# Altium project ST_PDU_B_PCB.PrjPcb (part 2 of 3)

## Sheet GroupB.SchDoc: ST PDU - Group B
size A3; Author: EMEA - ADG - M&A; Organization: STMicroelectronics; Address1: Pobrezni 3; Address2: 186 00  Prague 8; Address3: Czech Republic; Revision: 2.3; SheetNumber: 8; SheetTotal: 14
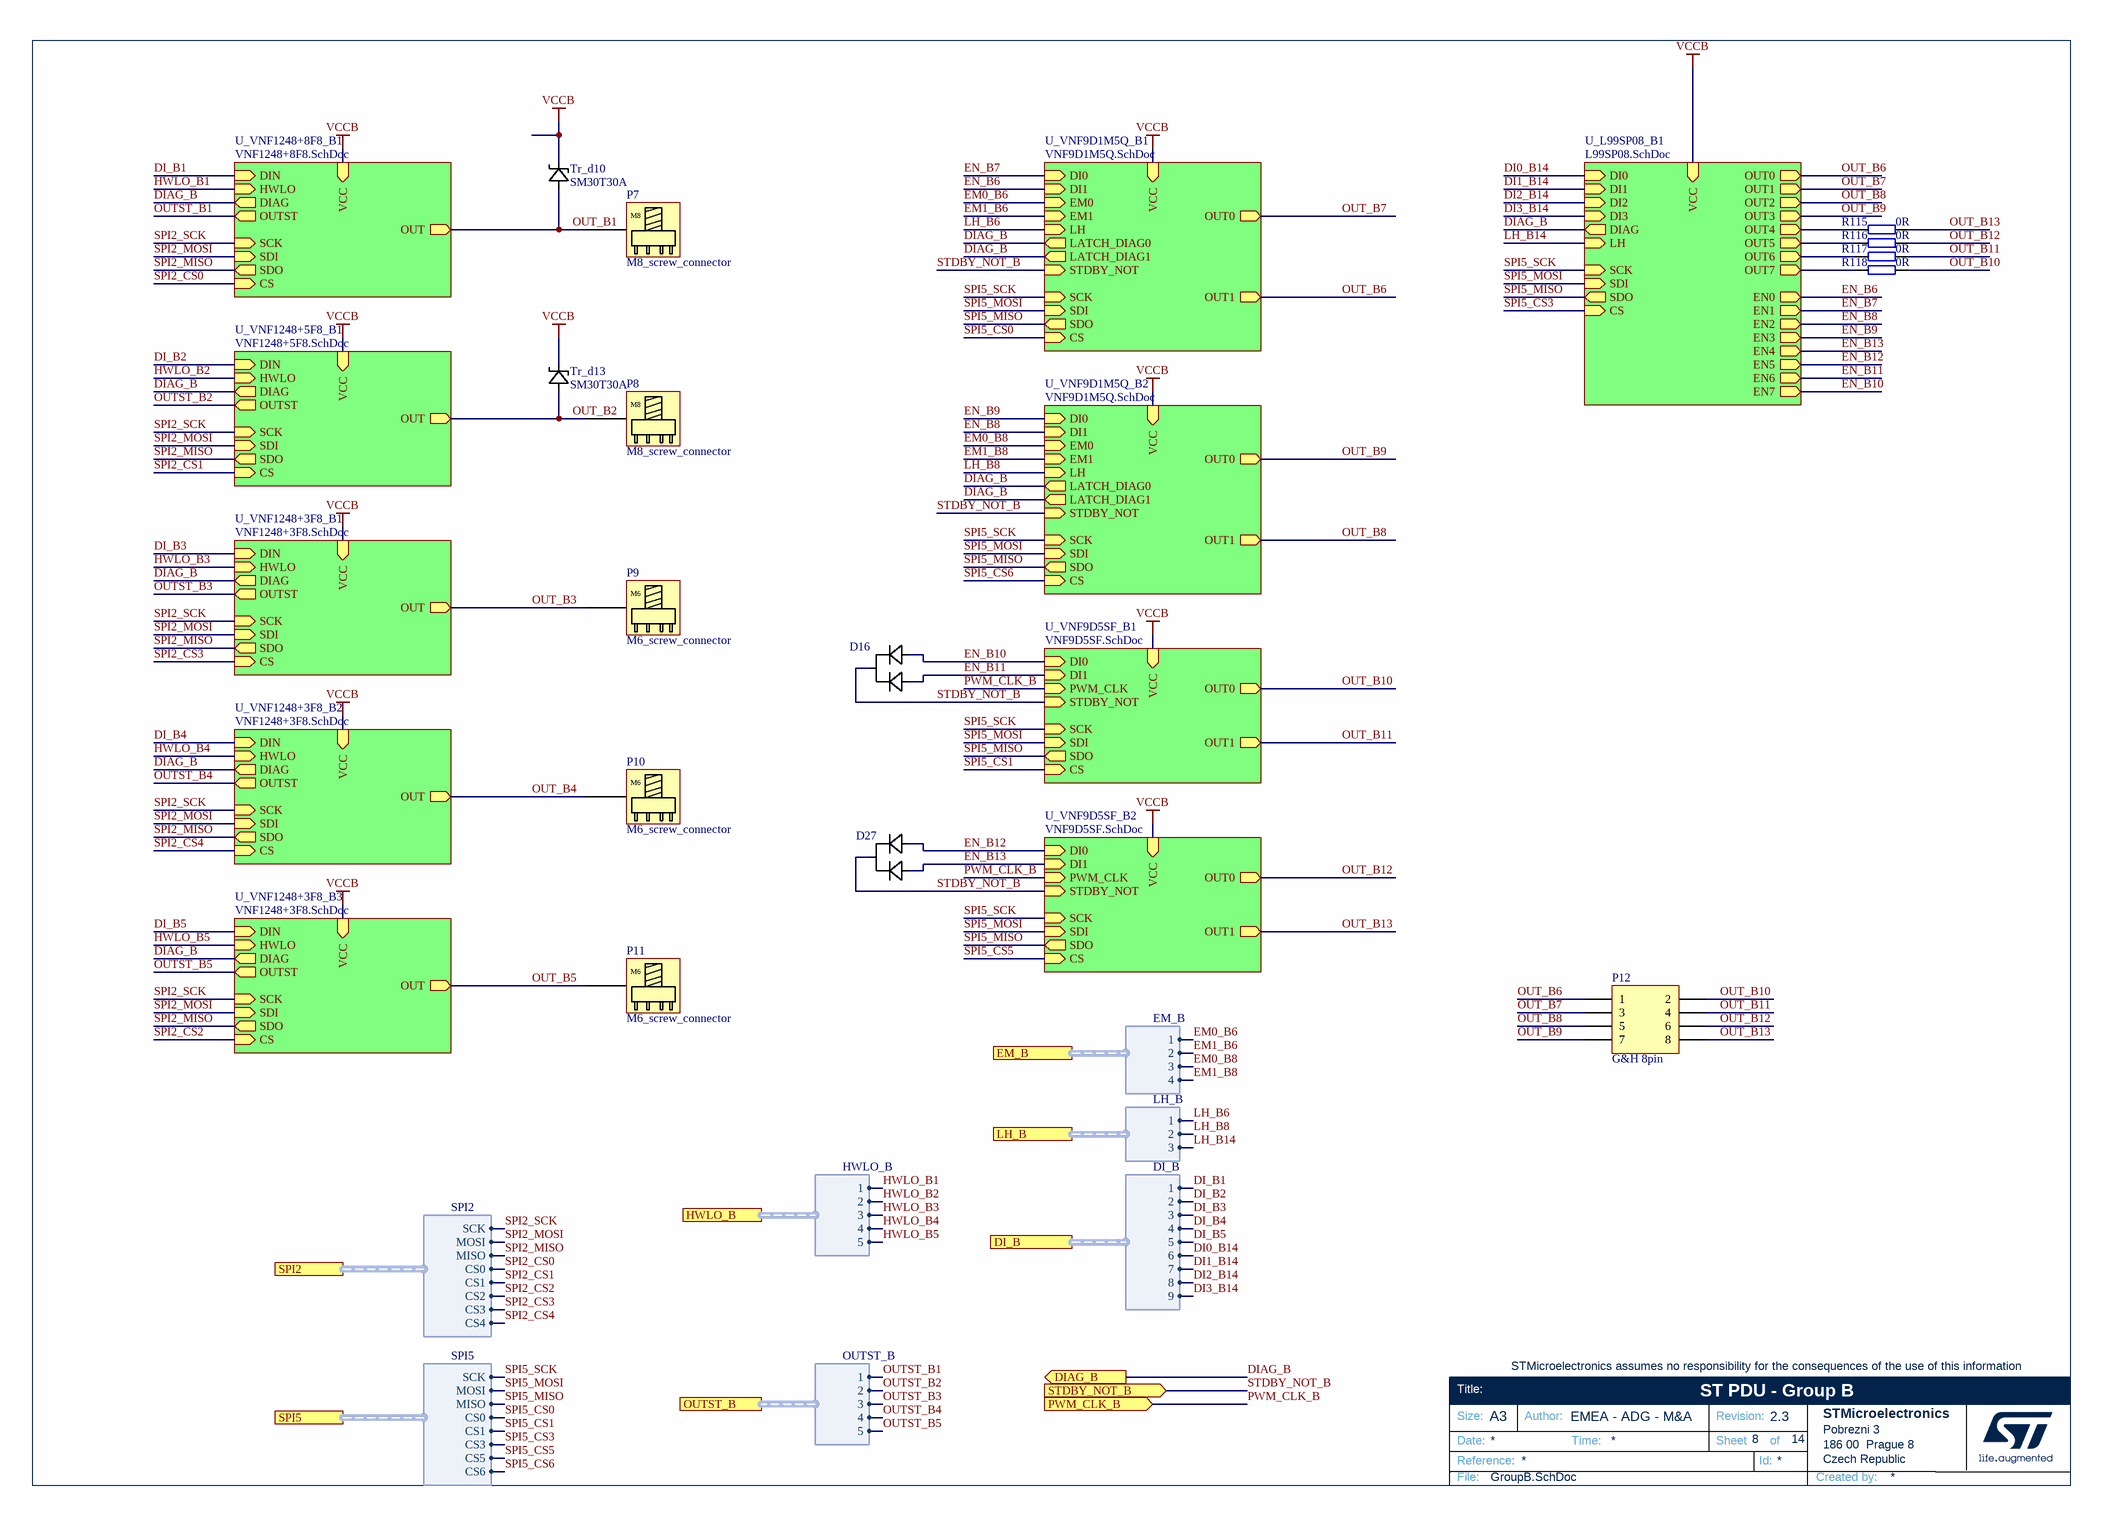
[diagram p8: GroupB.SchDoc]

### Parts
D16  BAT54-Y  [SOT323-3L_STM]  (value not drawn)
D27  BAT54-Y  [SOT323-3L_STM]  (value not drawn)
P7  M8_screw_connector  [MTConn Power Tower M8]
P8  M8_screw_connector  [MTConn Power Tower M8]
P9  M6_screw_connector  [MTConn Power Tower M6]
P10  M6_screw_connector  [MTConn Power Tower M6]
P11  M6_screw_connector  [MTConn Power Tower M6]
P12  value G&H 8pin  [MTConn GH 8pin]  (hidden comment: GH 8pin)
R115  0R  [R0603_round]
R116  0R  [R0603_round]
R117  0R  [R0603_round]
R118  0R  [R0603_round]
Tr_d10  SM30T30A  [SMC]
Tr_d13  SM30T30A  [SMC]

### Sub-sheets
U_L99SP08_B1 = L99SP08.SchDoc: CS (in), SCK (in), SDI (in), SDO (out), OUT1 (out), OUT2 (out), OUT3 (out), OUT0 (out), DI0 (in), DI1 (in), DI2 (in), DI3 (in), LH (in), DIAG (out), VCC (in), EN1 (out), EN2 (out), EN3 (out), EN0 (out), EN5 (out), EN6 (out), EN7 (out), EN4 (out), OUT5 (out), OUT6 (out), OUT7 (out), OUT4 (out)
U_VNF9D1M5Q_B1 = VNF9D1M5Q.SchDoc: CS (in), OUT0 (out), OUT1 (out), SCK (in), SDI (in), SDO (out), EM0 (in), EM1 (in), DI0 (in), DI1 (in), LATCH_DIAG0 (out), LATCH_DIAG1 (out), LH (in), VCC (in), STDBY_NOT (in)
U_VNF9D1M5Q_B2 = VNF9D1M5Q.SchDoc: CS (in), OUT0 (out), OUT1 (out), SCK (in), SDI (in), SDO (out), EM0 (in), EM1 (in), DI0 (in), DI1 (in), LATCH_DIAG0 (out), LATCH_DIAG1 (out), LH (in), VCC (in), STDBY_NOT (in)
U_VNF9D5SF_B1 = VNF9D5SF.SchDoc: OUT0 (out), OUT1 (out), VCC (in), CS (in), SCK (in), SDI (in), SDO (out), DI0 (in), DI1 (in), PWM_CLK (in), STDBY_NOT (in)
U_VNF9D5SF_B2 = VNF9D5SF.SchDoc: OUT0 (out), OUT1 (out), VCC (in), CS (in), SCK (in), SDI (in), SDO (out), DI0 (in), DI1 (in), PWM_CLK (in), STDBY_NOT (in)
U_VNF1248+3F8_B1 = VNF1248+3F8.SchDoc: OUT (out), VCC (in), CS (in), SCK (in), SDI (in), SDO (out), DIAG (out), HWLO (in), DIN (in), OUTST (out)
U_VNF1248+3F8_B2 = VNF1248+3F8.SchDoc: OUT (out), VCC (in), CS (in), SCK (in), SDI (in), SDO (out), DIAG (out), HWLO (in), DIN (in), OUTST (out)
U_VNF1248+3F8_B3 = VNF1248+3F8.SchDoc: OUT (out), VCC (in), CS (in), SCK (in), SDI (in), SDO (out), DIAG (out), HWLO (in), DIN (in), OUTST (out)
U_VNF1248+5F8_B1 = VNF1248+5F8.SchDoc: OUT (out), VCC (in), CS (in), SCK (in), SDI (in), SDO (out), DIAG (out), HWLO (in), DIN (in), OUTST (out)
U_VNF1248+8F8_B1 = VNF1248+8F8.SchDoc: OUT (out), VCC (in), CS (in), SCK (in), SDI (in), SDO (out), DIAG (out), HWLO (in), DIN (in), OUTST (out)

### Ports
DI_B (harness DI_B, see TOP_level[3B], MCU[7A]), DIAG_B (out, see TOP_level[3B], MCU[8B], PMIC[3D]), EM_B (harness EM_B, see TOP_level[3B], MCU[7A]), HWLO_B (harness HWLO_B, see TOP_level[3B], MCU[7B]), LH_B (harness LH_B, see TOP_level[3B], MCU[7A]), OUTST_B (harness OUTST_B, see TOP_level[3B], MCU[7B]), PWM_CLK_B (in, see TOP_level[3B], MCU[8B]), SPI2 (harness SPI2, see TOP_level[3B], MCU[7C]), SPI5 (harness SPI5, see TOP_level[3B], MCU[7D]), STDBY_NOT_B (in, see TOP_level[3B], MCU[8B])

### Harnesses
SPI2: SCK, MOSI, MISO, CS0, CS1, CS2, CS3, CS4
SPI5: SCK, MOSI, MISO, CS0, CS1, CS3, CS5, CS6
HWLO_B: 1, 2, 3, 4, 5
DI_B: 1, 2, 3, 4, 5, 6, 7, 8, 9
OUTST_B: 1, 2, 3, 4, 5
LH_B: 1, 2, 3
EM_B: 1, 2, 3, 4

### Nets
VCCB: Tr_d10.C Tr_d13.C ; sheet U_VNF1248+8F8_B1/VCC, sheet U_VNF1248+5F8_B1/VCC, sheet U_VNF1248+3F8_B1/VCC, sheet U_VNF1248+3F8_B2/VCC, sheet U_VNF1248+3F8_B3/VCC, sheet U_VNF9D1M5Q_B1/VCC, sheet U_VNF9D1M5Q_B2/VCC, sheet U_L99SP08_B1/VCC, sheet U_VNF9D5SF_B1/VCC, sheet U_VNF9D5SF_B2/VCC
DI0_B14: sheet U_L99SP08_B1/DI0, port DI_B.6
DI1_B14: sheet U_L99SP08_B1/DI1, port DI_B.7
DI2_B14: sheet U_L99SP08_B1/DI2, port DI_B.8
DI3_B14: sheet U_L99SP08_B1/DI3, port DI_B.9
DI_B1: sheet U_VNF1248+8F8_B1/DIN, port DI_B.1
DI_B2: sheet U_VNF1248+5F8_B1/DIN, port DI_B.2
DI_B3: sheet U_VNF1248+3F8_B1/DIN, port DI_B.3
DI_B4: sheet U_VNF1248+3F8_B2/DIN, port DI_B.4
DI_B5: sheet U_VNF1248+3F8_B3/DIN, port DI_B.5
DIAG_B: port DIAG_B, sheet U_VNF1248+8F8_B1/DIAG, sheet U_VNF1248+5F8_B1/DIAG, sheet U_VNF1248+3F8_B1/DIAG, sheet U_VNF1248+3F8_B2/DIAG, sheet U_VNF1248+3F8_B3/DIAG, sheet U_VNF9D1M5Q_B1/LATCH_DIAG0, sheet U_VNF9D1M5Q_B1/LATCH_DIAG1, sheet U_VNF9D1M5Q_B2/LATCH_DIAG0, sheet U_VNF9D1M5Q_B2/LATCH_DIAG1, sheet U_L99SP08_B1/DIAG
EM0_B6: sheet U_VNF9D1M5Q_B1/EM0, port EM_B.1
EM0_B8: sheet U_VNF9D1M5Q_B2/EM0, port EM_B.3
EM1_B6: sheet U_VNF9D1M5Q_B1/EM1, port EM_B.2
EM1_B8: sheet U_VNF9D1M5Q_B2/EM1, port EM_B.4
EN_B6: sheet U_VNF9D1M5Q_B1/DI1, sheet U_L99SP08_B1/EN0
EN_B7: sheet U_VNF9D1M5Q_B1/DI0, sheet U_L99SP08_B1/EN1
EN_B8: sheet U_VNF9D1M5Q_B2/DI1, sheet U_L99SP08_B1/EN2
EN_B9: sheet U_VNF9D1M5Q_B2/DI0, sheet U_L99SP08_B1/EN3
EN_B10: D16.2 ; sheet U_L99SP08_B1/EN7, sheet U_VNF9D5SF_B1/DI0
EN_B11: D16.1 ; sheet U_L99SP08_B1/EN6, sheet U_VNF9D5SF_B1/DI1
EN_B12: D27.2 ; sheet U_L99SP08_B1/EN5, sheet U_VNF9D5SF_B2/DI0
EN_B13: D27.1 ; sheet U_L99SP08_B1/EN4, sheet U_VNF9D5SF_B2/DI1
HWLO_B1: sheet U_VNF1248+8F8_B1/HWLO, port HWLO_B.1
HWLO_B2: sheet U_VNF1248+5F8_B1/HWLO, port HWLO_B.2
HWLO_B3: sheet U_VNF1248+3F8_B1/HWLO, port HWLO_B.3
HWLO_B4: sheet U_VNF1248+3F8_B2/HWLO, port HWLO_B.4
HWLO_B5: sheet U_VNF1248+3F8_B3/HWLO, port HWLO_B.5
LH_B6: sheet U_VNF9D1M5Q_B1/LH, port LH_B.1
LH_B8: sheet U_VNF9D1M5Q_B2/LH, port LH_B.2
LH_B14: sheet U_L99SP08_B1/LH, port LH_B.3
OUT_B1: P7.1 Tr_d10.A ; sheet U_VNF1248+8F8_B1/OUT
OUT_B2: P8.1 Tr_d13.A ; sheet U_VNF1248+5F8_B1/OUT
OUT_B3: P9.1 ; sheet U_VNF1248+3F8_B1/OUT
OUT_B4: P10.1 ; sheet U_VNF1248+3F8_B2/OUT
OUT_B5: P11.1 ; sheet U_VNF1248+3F8_B3/OUT
OUT_B6: P12.1 ; sheet U_VNF9D1M5Q_B1/OUT1, sheet U_L99SP08_B1/OUT0
OUT_B7: P12.3 ; sheet U_VNF9D1M5Q_B1/OUT0, sheet U_L99SP08_B1/OUT1
OUT_B8: P12.5 ; sheet U_VNF9D1M5Q_B2/OUT1, sheet U_L99SP08_B1/OUT2
OUT_B9: P12.7 ; sheet U_VNF9D1M5Q_B2/OUT0, sheet U_L99SP08_B1/OUT3
OUT_B10: P12.2 R118.1 ; sheet U_VNF9D5SF_B1/OUT0
OUT_B11: P12.4 R117.1 ; sheet U_VNF9D5SF_B1/OUT1
OUT_B12: P12.6 R116.1 ; sheet U_VNF9D5SF_B2/OUT0
OUT_B13: P12.8 R115.1 ; sheet U_VNF9D5SF_B2/OUT1
OUTST_B1: sheet U_VNF1248+8F8_B1/OUTST, port OUTST_B.1
OUTST_B2: sheet U_VNF1248+5F8_B1/OUTST, port OUTST_B.2
OUTST_B3: sheet U_VNF1248+3F8_B1/OUTST, port OUTST_B.3
OUTST_B4: sheet U_VNF1248+3F8_B2/OUTST, port OUTST_B.4
OUTST_B5: sheet U_VNF1248+3F8_B3/OUTST, port OUTST_B.5
PWM_CLK_B: port PWM_CLK_B, sheet U_VNF9D5SF_B1/PWM_CLK, sheet U_VNF9D5SF_B2/PWM_CLK
SPI2_CS0: sheet U_VNF1248+8F8_B1/CS, port SPI2.CS0
SPI2_CS1: sheet U_VNF1248+5F8_B1/CS, port SPI2.CS1
SPI2_CS2: sheet U_VNF1248+3F8_B3/CS, port SPI2.CS2
SPI2_CS3: sheet U_VNF1248+3F8_B1/CS, port SPI2.CS3
SPI2_CS4: sheet U_VNF1248+3F8_B2/CS, port SPI2.CS4
SPI2_MISO: sheet U_VNF1248+8F8_B1/SDO, sheet U_VNF1248+5F8_B1/SDO, sheet U_VNF1248+3F8_B1/SDO, sheet U_VNF1248+3F8_B2/SDO, sheet U_VNF1248+3F8_B3/SDO, port SPI2.MISO
SPI2_MOSI: sheet U_VNF1248+8F8_B1/SDI, sheet U_VNF1248+5F8_B1/SDI, sheet U_VNF1248+3F8_B1/SDI, sheet U_VNF1248+3F8_B2/SDI, sheet U_VNF1248+3F8_B3/SDI, port SPI2.MOSI
SPI2_SCK: sheet U_VNF1248+8F8_B1/SCK, sheet U_VNF1248+5F8_B1/SCK, sheet U_VNF1248+3F8_B1/SCK, sheet U_VNF1248+3F8_B2/SCK, sheet U_VNF1248+3F8_B3/SCK, port SPI2.SCK
SPI5_CS0: sheet U_VNF9D1M5Q_B1/CS, port SPI5.CS0
SPI5_CS1: sheet U_VNF9D5SF_B1/CS, port SPI5.CS1
SPI5_CS3: sheet U_L99SP08_B1/CS, port SPI5.CS3
SPI5_CS5: sheet U_VNF9D5SF_B2/CS, port SPI5.CS5
SPI5_CS6: sheet U_VNF9D1M5Q_B2/CS, port SPI5.CS6
SPI5_MISO: sheet U_VNF9D1M5Q_B1/SDO, sheet U_VNF9D1M5Q_B2/SDO, sheet U_L99SP08_B1/SDO, sheet U_VNF9D5SF_B1/SDO, sheet U_VNF9D5SF_B2/SDO, port SPI5.MISO
SPI5_MOSI: sheet U_VNF9D1M5Q_B1/SDI, sheet U_VNF9D1M5Q_B2/SDI, sheet U_L99SP08_B1/SDI, sheet U_VNF9D5SF_B1/SDI, sheet U_VNF9D5SF_B2/SDI, port SPI5.MOSI
SPI5_SCK: sheet U_VNF9D1M5Q_B1/SCK, sheet U_VNF9D1M5Q_B2/SCK, sheet U_L99SP08_B1/SCK, sheet U_VNF9D5SF_B1/SCK, sheet U_VNF9D5SF_B2/SCK, port SPI5.SCK
STDBY_NOT_B: D16.3 D27.3 ; port STDBY_NOT_B, sheet U_VNF9D1M5Q_B1/STDBY_NOT, sheet U_VNF9D1M5Q_B2/STDBY_NOT, sheet U_VNF9D5SF_B1/STDBY_NOT, sheet U_VNF9D5SF_B2/STDBY_NOT
NetR115_2: R115.2 ; sheet U_L99SP08_B1/OUT4
NetR116_2: R116.2 ; sheet U_L99SP08_B1/OUT5
NetR117_2: R117.2 ; sheet U_L99SP08_B1/OUT6
NetR118_2: R118.2 ; sheet U_L99SP08_B1/OUT7

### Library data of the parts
D16 D27 = BAT54C: Automotive small signal dual Schottky diodes with common cathode; Forward Drop: 0,5V; T.Min: -40C; T.Max: 150C; Value: 40V; Current: 0.3A
P7 P8 = M8_screw_connector: Pressfit M8 screw power connector (max 170A) with protector
P9-P11 = M6_screw_connector: Pressfit M6 screw power connector (max 80A) with protector
P12 = GH 8pin: MTCon G&H 8pin power connector (max 40A/pin). Pressfit; Model: TSW-110-07-G-S
R115-R118 = 0R/0.1W_5%_0603: Resistor SMD; Tolerance: 5%; Power: 0.1W
Tr_d10 Tr_d13 = SM30T30A: 30V 3000W unidirectional TVS in SMC; T.Min: -55C; T.Max: +150C

## Sheet VNF9D5SF.SchDoc: ST PDU - VNF9D5SF
size A4; Author: EMEA - ADG - M&A; Organization: STMicroelectronics; Address1: Pobrezni 3; Address2: 186 00  Prague 8; Address3: Czech Republic; Revision: 2.3; SheetNumber: 10; SheetTotal: 14
Used 2 times, as channels U_GroupB/U_VNF9D5SF_B1, U_GroupB/U_VNF9D5SF_B2. Parts and nets are listed once, with the designators drawn on the sheet.
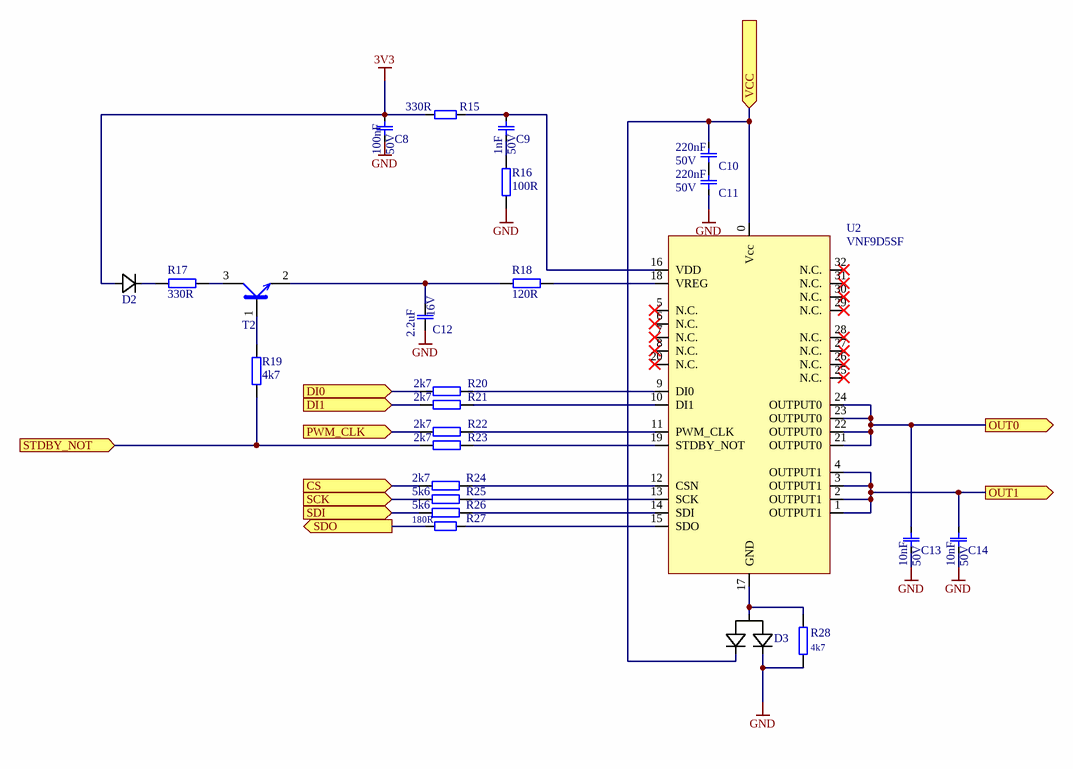
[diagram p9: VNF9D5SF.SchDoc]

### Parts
C8  Voltage: 50V  [C0603_ROUND]  (hidden comment: 100nF)
C9  Voltage: 50V  [C0603_ROUND]  (hidden comment: 1nF)
C10  Voltage: 50V  [C0603_ROUND]  (hidden comment: 220nF)
C11  Voltage: 50V  [C0603_ROUND]  (hidden comment: 220nF)
C12  Voltage: 16V  [C0603_ROUND]  (hidden comment: 2.2uF)
C13  Voltage: 50V  [C0603_ROUND]  (hidden comment: 10nF)
C14  Voltage: 50V  [C0603_ROUND]  (hidden comment: 10nF)
D2  BAT54-Y  [SOT323-3L_STM]  (value not drawn)
D3  BAT54A  [SOT323-3L_STM]  (value not drawn)
R15  330R  [R0805_ROUND]
R16  100R  [R0603_round]
R17  330R  [R0603_round]
R18  120R  [R0603_round]
R19  4k7  [R0603_round]
R20  2k7  [R0603_round]
R21  2k7  [R0603_round]
R22  2k7  [R0603_round]
R23  2k7  [R0603_round]
R24  2k7  [R0603_round]
R25  5k6  [R0603_round]
R26  5k6  [R0603_round]
R27  180R  [R0603_round]
R28  4k7  [R0603_round]
T2  BC847  [SOT323-3L_STM]  (value not drawn)
U2  VNF9D5SF  [QFN6x6_VN9D30_STM]

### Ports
CS (in, see GroupB[4C]), DI0 (in, see GroupB[4B]), DI1 (in, see GroupB[4B]), OUT0 (out, see GroupB[5B]), OUT1 (out, see GroupB[5B]), PWM_CLK (in, see GroupB[4B]), SCK (in, see GroupB[4B], L99SP08[2C], VNF9D1M5Q[2C]), SDI (in, see GroupB[4B], L99SP08[2C], VNF9D1M5Q[2C]), SDO (out, see GroupB[4B], L99SP08[2C], VNF9D1M5Q[2C]), STDBY_NOT (in, see GroupB[4B], VNF9D1M5Q[1B]), VCC (in, see GroupB[5B], L99SP08[2A], VNF9D1M5Q[3A], VNF1248+3F8[3A], VNF1248+5F8[3A], VNF1248+8F8[2A])

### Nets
3V3: C8.2 D2.A R15.1
GND: C8.1 C11.1 C12.1 C13.1 C14.1 D3.2 R16.2 R28.2
CS: R24.2 ; port CS
DI0: R20.2 ; port DI0
DI1: R21.2 ; port DI1
OUT0: C13.2 U2.21(OUTPUT0) U2.22(OUTPUT0) U2.23(OUTPUT0) U2.24(OUTPUT0) ; port OUT0
OUT1: C14.2 U2.1(OUTPUT1) U2.2(OUTPUT1) U2.3(OUTPUT1) U2.4(OUTPUT1) ; port OUT1
PWM_CLK: R22.2 ; port PWM_CLK
SCK: R25.2 ; port SCK
SDI: R26.2 ; port SDI
SDO: R27.1 ; port SDO
STDBY_NOT: R19.2 R23.2 ; port STDBY_NOT
VCC: C10.2 D3.1 U2.0(Vcc) ; port VCC
NetC9_1: C9.1 R16.1
NetC9_2: C9.2 R15.2 U2.16(VDD)
NetC10_1: C10.1 C11.2
NetC12_2: C12.2 R18.1 T2.2(E)
NetD2_C: D2.C R17.1
NetD3_3: D3.3 R28.1 U2.17(GND)
NetR17_2: R17.2 T2.3(C)
NetR18_2: R18.2 U2.18(VREG)
NetR19_1: R19.1 T2.1(B)
NetR20_1: R20.1 U2.9(DI0)
NetR21_1: R21.1 U2.10(DI1)
NetR22_1: R22.1 U2.11(PWM_CLK)
NetR23_1: R23.1 U2.19(STDBY_NOT)
NetR24_1: R24.1 U2.12(CSN)
NetR25_1: R25.1 U2.13(SCK)
NetR26_1: R26.1 U2.14(SDI)
NetR27_2: R27.2 U2.15(SDO)

Not connected (* = marked no-connect by the designer): U2 5(N.C.)* 6(N.C.)* 7(N.C.)* 8(N.C.)* 20(N.C.)* 25(N.C.)* 26(N.C.)* 27(N.C.)* 28(N.C.)* 29(N.C.)* 30(N.C.)* 31(N.C.)* 32(N.C.)*

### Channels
U_GroupB/U_VNF9D5SF_B1: designators end in A; ports CS=SPI5_CS1 DI0=EN_B10 DI1=EN_B11 OUT0=OUT_B10 OUT1=OUT_B11 PWM_CLK=PWM_CLK_B SCK=SPI5_SCK SDI=SPI5_MOSI SDO=SPI5_MISO STDBY_NOT=STDBY_NOT_B VCC=VCCB
U_GroupB/U_VNF9D5SF_B2: designators end in B; ports CS=SPI5_CS5 DI0=EN_B12 DI1=EN_B13 OUT0=OUT_B12 OUT1=OUT_B13 PWM_CLK=PWM_CLK_B SCK=SPI5_SCK SDI=SPI5_MOSI SDO=SPI5_MISO STDBY_NOT=STDBY_NOT_B VCC=VCCB

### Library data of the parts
C8 = 100nF/50V_10%_0603: 100nF Ceramic capacitor; Tolerance: 10%; T.Min: -55C; T.Max: 125C; Type: X7R
C9 = 1nF/50V_10%_0603: 1nF Ceramic capacitor; Tolerance: 10%; T.Min: -55C; T.Max: 125C; Type: X7R
C10 C11 = 220nF/50V_10%_0603: 220nF Ceramic capacitor; Tolerance: 10%; T.Min: -55C; T.Max: 125C; Type: X7R
C12 = 2.2uF/16V_10%_0603: 2.2uF Ceramic capacitor; Tolerance: 10%; T.Min: -55C; T.Max: 125C; Type: X7R
C13 C14 = 10nF/50V_10%_0603: 10nF Ceramic capacitor; Tolerance: 10%; T.Min: -55C; T.Max: 125C; Type: X7R
D2 = BAT54-Y: Automotive small signal Schottky diodes; pin to pad: A>1 C>3; Forward Drop: 0,5V; T.Min: -40C; T.Max: 150C; Value: 40V; Current: 0.3A
D3 = BAT54A: Automotive small signal dual Schottky diodes with common anode; Forward Drop: 0,5V; T.Min: -40C; T.Max: 150C; Value: 40V; Current: 0.3A
R15 = 330R/150V_1%_0805: Resistor SMD 0805; Tolerance: 1%; Voltage: 150V; Power Rating Per Resistor: 125mW; T.Min: -55C; T.Max: 155C
R16 = 100R/0.1W_5%_0603: Resistor SMD; Tolerance: 5%; Power: 0.1W
R17 = 330R/0.1W_5%_0603: Resistor SMD; Tolerance: 5%; Power: 0.1W
R18 = 120R/0.1W_5%_0603: Resistor SMD; Tolerance: 5%; Power: 0.1W
R19 R28 = 4k7/0.1W_5%_0603: Resistor SMD; Tolerance: 5%; Power: 0.1W
R20-R24 = 2k7/0.1W_5%_0603: Resistor SMD; Tolerance: 5%; Power: 0.1W
R25 R26 = 5k6/0.1W_5%_0603: Resistor SMD; Tolerance: 5%; Power: 0.1W
R27 = 180R/0.1W_5%_0603: Resistor SMD 0603; Tolerance: 5%; Power: 0.1W
T2 = BC847: NPN

## Sheet MCU.SchDoc: ST DPU - MCU
size A3; Author: EMEA - ADG - M&A; Organization: STMicroelectronics; Address1: Pobrezni 3; Address2: 186 00  Prague 8; Address3: Czech Republic; Revision: 2.3; SheetNumber: 11; SheetTotal: 14
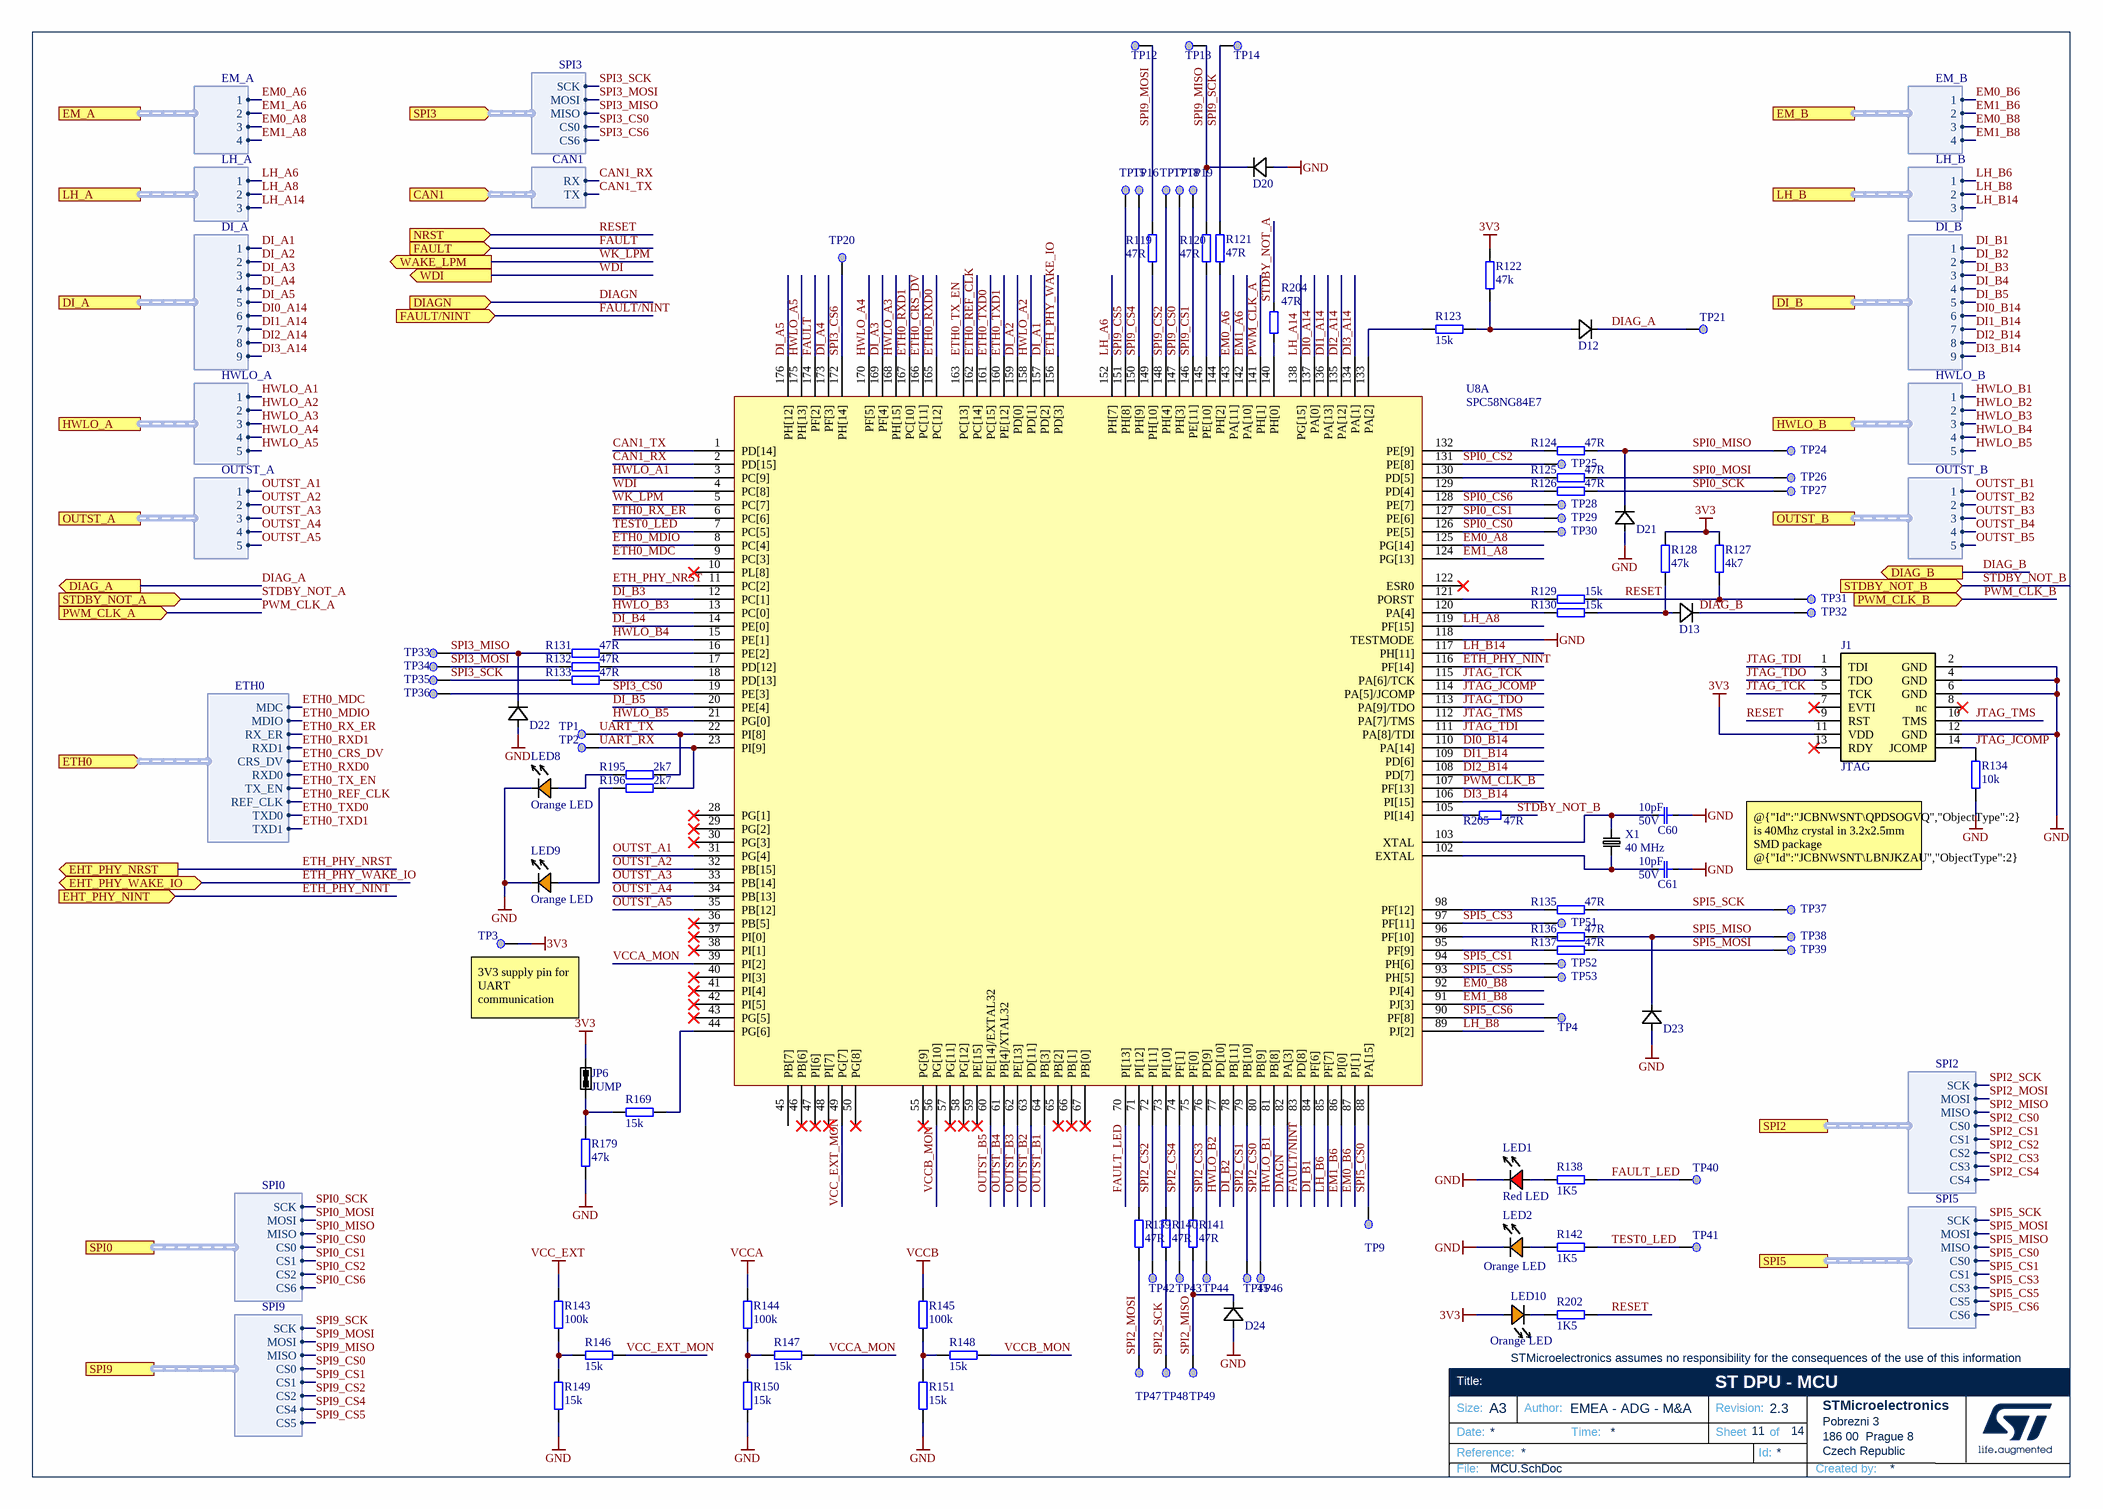
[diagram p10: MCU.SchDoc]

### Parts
C60  Voltage: 50V  [C0603_ROUND]  (hidden comment: 10pF)
C61  Voltage: 50V  [C0603_ROUND]  (hidden comment: 10pF)
D12  BAT54-Y  [SOT323-3L_STM]  (value not drawn)
D13  BAT54-Y  [SOT323-3L_STM]  (value not drawn)
D20  BAT54-Y  [SOT323-3L_STM]  (value not drawn)
D21  BAT54-Y  [SOT323-3L_STM]  (value not drawn)
D22  BAT54-Y  [SOT323-3L_STM]  (value not drawn)
D23  BAT54-Y  [SOT323-3L_STM]  (value not drawn)
D24  BAT54-Y  [SOT323-3L_STM]  (value not drawn)
J1  value JTAG  [MLW14]  (hidden comment: JTAG_PPC)
JP6  JUMP  [JUMP_2]
LED1  Red LED  [D0603_ROUND]
LED2  Orange LED  [D0603_ROUND]
LED8  Orange LED  [D0603_ROUND]
LED9  Orange LED  [D0603_ROUND]
LED10  Orange LED  [D0603_ROUND]
R119  47R  [R0603_round]
R120  47R  [R0603_round]
R121  47R  [R0603_round]
R122  47k  [R0603_round]
R123  15k  [R0603_round]
R124  47R  [R0603_round]
R125  47R  [R0603_round]
R126  47R  [R0603_round]
R127  4k7  [R0603_round]
R128  47k  [R0603_round]
R129  15k  [R0603_round]
R130  15k  [R0603_round]
R131  47R  [R0603_round]
R132  47R  [R0603_round]
R133  47R  [R0603_round]
R134  10k  [R0603_round]
R135  47R  [R0603_round]
R136  47R  [R0603_round]
R137  47R  [R0603_round]
R138  1K5  [R0603_round]
R139  47R  [R0603_round]
R140  47R  [R0603_round]
R141  47R  [R0603_round]
R142  1K5  [R0603_round]
R143  100k  [R0603_round]
R144  100k  [R0603_round]
R145  100k  [R0603_round]
R146  15k  [R0603_round]
R147  15k  [R0603_round]
R148  15k  [R0603_round]
R149  15k  [R0603_round]
R150  15k  [R0603_round]
R151  15k  [R0603_round]
R169  15k  [R0603_round]
R179  47k  [R0603_round]
R195  2k7  [R0603_round]
R196  2k7  [R0603_round]
R202  1K5  [R0603_round]
R204  47R  [R0603_round]
R205  47R  [R0603_round]
TP1  UART_TX  [PIN]  (value not drawn)
TP2  UART_RX  [PIN]  (value not drawn)
TP3  UART_3V3  [PIN]  (value not drawn)
TP4  SPI2_MOSI  [PIN]  (value not drawn)
TP9  SPI2_MOSI  [PIN]  (value not drawn)
TP12  SPI9_MOSI  [PIN]  (value not drawn)
TP13  SPI9_MISO  [PIN]  (value not drawn)
TP14  SPI9_SCK  [PIN]  (value not drawn)
TP15  SPI9_CS5  [PIN]  (value not drawn)
TP16  SPI9_CS4  [PIN]  (value not drawn)
TP17  SPI9_CS2  [PIN]  (value not drawn)
TP18  SPI9_CS0  [PIN]  (value not drawn)
TP19  SPI9_CS1  [PIN]  (value not drawn)
TP20  SPI3_CS6  [PIN]  (value not drawn)
TP21  DIAG_A  [PIN]  (value not drawn)
TP24  SPI0_MISO  [PIN]  (value not drawn)
TP25  SPI0_CS6  [PIN]  (value not drawn)
TP26  SPI0_MOSI  [PIN]  (value not drawn)
TP27  SPI0_SCK  [PIN]  (value not drawn)
TP28  SPI0_CS2  [PIN]  (value not drawn)
TP29  SPI0_CS6  [PIN]  (value not drawn)
TP30  SPI0_CS6  [PIN]  (value not drawn)
TP31  RST  [PIN]  (value not drawn)
TP32  DIAG_B  [PIN]  (value not drawn)
TP33  SPI3_MISO  [PIN]  (value not drawn)
TP34  SPI3_MOSI  [PIN]  (value not drawn)
TP35  SPI3_SCK  [PIN]  (value not drawn)
TP36  SPI3_CS0  [PIN]  (value not drawn)
TP37  SPI5_SCK  [PIN]  (value not drawn)
TP38  SPI5_MISO  [PIN]  (value not drawn)
TP39  SPI5_MOSI  [PIN]  (value not drawn)
TP40  FAULT  [PIN]  (value not drawn)
TP41  TEST0  [PIN]  (value not drawn)
TP42  SPI2_CS2  [PIN]  (value not drawn)
TP43  SPI2_CS4  [PIN]  (value not drawn)
TP44  SPI2_CS3  [PIN]  (value not drawn)
TP45  SPI2_CS1  [PIN]  (value not drawn)
TP46  SPI2_CS0  [PIN]  (value not drawn)
TP47  SPI2_MOSI  [PIN]  (value not drawn)
TP48  SPI2_SCK  [PIN]  (value not drawn)
TP49  SPI2_MISO  [PIN]  (value not drawn)
TP51  SPI5_CS3  [PIN]  (value not drawn)
TP52  SPI5_CS1  [PIN]  (value not drawn)
TP53  SPI5_CS5  [PIN]  (value not drawn)
U8  SPC58NG84E7  [eLQFP176 (LQFP176L2600X2600-176)]  (part A of 2)
X1  value 40 MHz  [CRYSTAL_SMD_3.2x2.5mm]  (hidden comment: 40MHz)

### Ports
CAN1 (in, harness CAN1, see TOP_level[2C], PMIC[1D]), DI_A (harness DI_A, see TOP_level[2A], GroupA[4D]), DI_B (harness DI_B, see TOP_level[2B], GroupB[4D]), DIAG_A (out, see TOP_level[2B], GroupA[4D], PMIC[3D]), DIAG_B (out, see TOP_level[2B], GroupB[4D], PMIC[3D]), DIAGN (in, see TOP_level[2C], PMIC[6B]), EHT_PHY_NINT (in, see TOP_level[2C]), EHT_PHY_NRST (out, see TOP_level[2B]), EHT_PHY_WAKE_IO (bidir, see TOP_level[2C], Ethernet[1C]), EM_A (harness EM_A, see TOP_level[2A], GroupA[4C]), EM_B (harness EM_B, see TOP_level[2B], GroupB[4C]), ETH0 (in, harness ETH0, see TOP_level[2B], Ethernet[1B]), FAULT (in, see TOP_level[2C], PMIC[1D]), FAULT/NINT (in, see TOP_level[2C], PMIC[5B]), HWLO_A (harness HWLO_A, see TOP_level[2A], GroupA[2D]), HWLO_B (harness HWLO_B, see TOP_level[2B], GroupB[3D]), LH_A (harness LH_A, see TOP_level[2A], GroupA[4C]), LH_B (harness LH_B, see TOP_level[2B], GroupB[4C]), NRST (in, see TOP_level[2C], PMIC[5C]), OUTST_A (harness OUTST_A, see TOP_level[2A], GroupA[2D]), OUTST_B (harness OUTST_B, see TOP_level[2B], GroupB[3D]), PWM_CLK_A (in, see TOP_level[2A], GroupA[4D]), PWM_CLK_B (in, see TOP_level[2B], GroupB[4D]), SPI0 (harness SPI0, see TOP_level[2A], GroupA[1D]), SPI2 (harness SPI2, see TOP_level[2B], GroupB[2D]), SPI3 (in, harness SPI3, see TOP_level[2C], PMIC[1D]), SPI5 (harness SPI5, see TOP_level[2B], GroupB[2D]), SPI9 (harness SPI9, see TOP_level[2A], GroupA[1D]), STDBY_NOT_A (in, see TOP_level[2A], GroupA[4D]), STDBY_NOT_B (in, see TOP_level[2B], GroupB[4D]), WAKE_LPM (out, see TOP_level[2C], PMIC[1D]), WDI (out, see TOP_level[2C], PMIC[1D])

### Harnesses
SPI9: SCK, MOSI, MISO, CS0, CS1, CS2, CS4, CS5
SPI0: SCK, MOSI, MISO, CS0, CS1, CS2, CS6
HWLO_A: 1, 2, 3, 4, 5
DI_A: 1, 2, 3, 4, 5, 6, 7, 8, 9
OUTST_A: 1, 2, 3, 4, 5
LH_A: 1, 2, 3
EM_A: 1, 2, 3, 4
SPI2: SCK, MOSI, MISO, CS0, CS1, CS2, CS3, CS4
SPI5: SCK, MOSI, MISO, CS0, CS1, CS3, CS5, CS6
HWLO_B: 1, 2, 3, 4, 5
DI_B: 1, 2, 3, 4, 5, 6, 7, 8, 9
OUTST_B: 1, 2, 3, 4, 5
LH_B: 1, 2, 3
EM_B: 1, 2, 3, 4
ETH0: MDC, MDIO, RX_ER, RXD1, CRS_DV, RXD0, TX_EN, REF_CLK, TXD1, TXD0
SPI3: SCK, MOSI, MISO, CS0, CS6
CAN1: RX, TX

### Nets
3V3: J1.11(VDD) JP6.2 LED10.A R122.1 R127.1 R128.1 TP3.1
GND: C60.2 C61.2 D20.A D21.A D22.A D23.A D24.A J1.2(GND) J1.4(GND) J1.6(GND) J1.12(GND) LED1.C LED2.C LED8.C LED9.C R134.2 R149.2 R150.2 R151.2 R179.2 U8.118(TESTMODE)
VCC_EXT: R143.2
VCCA: R144.2
VCCB: R145.2
CAN1_RX: U8.2(PD[15]) ; port CAN1.RX
CAN1_TX: U8.1(PD[14]) ; port CAN1.TX
DI0_A14: U8.137(PA[0]) ; port DI_A.6
DI0_B14: U8.110(PA[14]) ; port DI_B.6
DI1_A14: U8.136(PA[13]) ; port DI_A.7
DI1_B14: U8.109(PD[6]) ; port DI_B.7
DI2_A14: U8.135(PA[12]) ; port DI_A.8
DI2_B14: U8.108(PD[7]) ; port DI_B.8
DI3_A14: U8.134(PA[1]) ; port DI_A.9
DI3_B14: U8.106(PI[15]) ; port DI_B.9
DI_A1: U8.157(PD[2]) ; port DI_A.1
DI_A2: U8.159(PD[0]) ; port DI_A.2
DI_A3: U8.169(PF[4]) ; port DI_A.3
DI_A4: U8.173(PF[3]) ; port DI_A.4
DI_A5: U8.176(PH[12]) ; port DI_A.5
DI_B1: U8.84(PF[6]) ; port DI_B.1
DI_B2: U8.78(PB[11]) ; port DI_B.2
DI_B3: U8.12(PC[1]) ; port DI_B.3
DI_B4: U8.14(PE[0]) ; port DI_B.4
DI_B5: U8.20(PE[4]) ; port DI_B.5
DIAG_A: D12.C TP21.1 ; port DIAG_A
DIAG_B: D13.C TP32.1 ; port DIAG_B
DIAGN: U8.82(PA[3]) ; port DIAGN
EM0_A6: U8.143(PA[11]) ; port EM_A.1
EM0_A8: U8.125(PG[14]) ; port EM_A.3
EM0_B6: U8.87(PJ[1]) ; port EM_B.1
EM0_B8: U8.92(PJ[4]) ; port EM_B.3
EM1_A6: U8.142(PA[10]) ; port EM_A.2
EM1_A8: U8.124(PG[13]) ; port EM_A.4
EM1_B6: U8.86(PJ[0]) ; port EM_B.2
EM1_B8: U8.91(PJ[3]) ; port EM_B.4
ETH0_CRS_DV: U8.166(PC[11]) ; port ETH0.CRS_DV
ETH0_MDC: U8.9(PC[3]) ; port ETH0.MDC
ETH0_MDIO: U8.8(PC[4]) ; port ETH0.MDIO
ETH0_REF_CLK: U8.162(PC[14]) ; port ETH0.REF_CLK
ETH0_RX_ER: U8.6(PC[6]) ; port ETH0.RX_ER
ETH0_RXD0: U8.165(PC[12]) ; port ETH0.RXD0
ETH0_RXD1: U8.167(PC[10]) ; port ETH0.RXD1
ETH0_TX_EN: U8.163(PC[13]) ; port ETH0.TX_EN
ETH0_TXD0: U8.161(PC[15]) ; port ETH0.TXD0
ETH0_TXD1: U8.160(PE[12]) ; port ETH0.TXD1
ETH_PHY_NINT: U8.116(PF[14]) ; port EHT_PHY_NINT
ETH_PHY_NRST: U8.11(PC[2]) ; port EHT_PHY_NRST
ETH_PHY_WAKE_IO: U8.156(PD[3]) ; port EHT_PHY_WAKE_IO
FAULT: U8.174(PF[2]) ; port FAULT
FAULT/NINT: U8.83(PD[8]) ; port FAULT/NINT
FAULT_LED: R138.1 TP40.1 U8.70(PI[13])
HWLO_A1: U8.3(PC[9]) ; port HWLO_A.1
HWLO_A2: U8.158(PD[1]) ; port HWLO_A.2
HWLO_A3: U8.168(PH[15]) ; port HWLO_A.3
HWLO_A4: U8.170(PF[5]) ; port HWLO_A.4
HWLO_A5: U8.175(PH[13]) ; port HWLO_A.5
HWLO_B1: U8.81(PB[8]) ; port HWLO_B.1
HWLO_B2: U8.77(PD[10]) ; port HWLO_B.2
HWLO_B3: U8.13(PC[0]) ; port HWLO_B.3
HWLO_B4: U8.15(PE[1]) ; port HWLO_B.4
HWLO_B5: U8.21(PG[0]) ; port HWLO_B.5
JTAG_JCOMP: J1.14(JCOMP) R134.1 U8.114(PA[5]/JCOMP)
JTAG_TCK: J1.5(TCK) U8.115(PA[6]/TCK)
JTAG_TDI: J1.1(TDI) U8.111(PA[8]/TDI)
JTAG_TDO: J1.3(TDO) U8.113(PA[9]/TDO)
JTAG_TMS: J1.10(TMS) U8.112(PA[7]/TMS)
LH_A6: U8.152(PH[7]) ; port LH_A.1
LH_A8: U8.119(PF[15]) ; port LH_A.2
LH_A14: U8.138(PG[15]) ; port LH_A.3
LH_B6: U8.85(PF[7]) ; port LH_B.1
LH_B8: U8.89(PJ[2]) ; port LH_B.2
LH_B14: U8.117(PH[11]) ; port LH_B.3
OUTST_A1: U8.31(PG[4]) ; port OUTST_A.1
OUTST_A2: U8.32(PB[15]) ; port OUTST_A.2
OUTST_A3: U8.33(PB[14]) ; port OUTST_A.3
OUTST_A4: U8.34(PB[13]) ; port OUTST_A.4
OUTST_A5: U8.35(PB[12]) ; port OUTST_A.5
OUTST_B1: U8.64(PB[3]) ; port OUTST_B.1
OUTST_B2: U8.63(PD[11]) ; port OUTST_B.2
OUTST_B3: U8.62(PE[13]) ; port OUTST_B.3
OUTST_B4: U8.61(PB[4]/XTAL32) ; port OUTST_B.4
OUTST_B5: U8.60(PE[14]/EXTAL32) ; port OUTST_B.5
PWM_CLK_A: U8.141(PH[1]) ; port PWM_CLK_A
PWM_CLK_B: U8.107(PF[13]) ; port PWM_CLK_B
RESET: J1.9(RST) R127.2 R129.2 R202.1 TP31.1 ; port NRST  [project net NRST]
SPI0_CS0: TP30.1 U8.126(PE[5]) ; port SPI0.CS0
SPI0_CS1: TP29.1 U8.127(PE[6]) ; port SPI0.CS1
SPI0_CS2: TP25.1 U8.131(PE[8]) ; port SPI0.CS2
SPI0_CS6: TP28.1 U8.128(PE[7]) ; port SPI0.CS6
SPI0_MISO: D21.C R124.2 TP24.1 ; port SPI0.MISO
SPI0_MOSI: R125.2 TP26.1 ; port SPI0.MOSI
SPI0_SCK: R126.2 TP27.1 ; port SPI0.SCK
SPI2_CS0: TP46.1 U8.80(PB[9]) ; port SPI2.CS0
SPI2_CS1: TP45.1 U8.79(PB[10]) ; port SPI2.CS1
SPI2_CS2: TP42.1 U8.72(PI[11]) ; port SPI2.CS2
SPI2_CS3: TP44.1 U8.76(PD[9]) ; port SPI2.CS3
SPI2_CS4: TP43.1 U8.74(PF[1]) ; port SPI2.CS4
SPI2_MISO: D24.C R141.2 TP49.1 ; port SPI2.MISO
SPI2_MOSI: R139.2 TP47.1 ; port SPI2.MOSI
SPI2_SCK: R140.2 TP48.1 ; port SPI2.SCK
SPI3_CS0: TP36.1 U8.19(PE[3]) ; port SPI3.CS0
SPI3_CS6: TP20.1 U8.172(PH[14]) ; port SPI3.CS6
SPI3_MISO: D22.C R131.1 TP33.1 ; port SPI3.MISO
SPI3_MOSI: R132.1 TP34.1 ; port SPI3.MOSI
SPI3_SCK: R133.1 TP35.1 ; port SPI3.SCK
SPI5_CS0: TP9.1 U8.88(PA[15]) ; port SPI5.CS0
SPI5_CS1: TP52.1 U8.94(PH[6]) ; port SPI5.CS1
SPI5_CS3: TP51.1 U8.97(PF[11]) ; port SPI5.CS3
SPI5_CS5: TP53.1 U8.93(PH[5]) ; port SPI5.CS5
SPI5_CS6: TP4.1 U8.90(PF[8]) ; port SPI5.CS6
SPI5_MISO: D23.C R136.2 TP38.1 ; port SPI5.MISO
SPI5_MOSI: R137.2 TP39.1 ; port SPI5.MOSI
SPI5_SCK: R135.2 TP37.1 ; port SPI5.SCK
SPI9_CS0: TP18.1 U8.147(PH[3]) ; port SPI9.CS0
SPI9_CS1: TP19.1 U8.146(PE[11]) ; port SPI9.CS1
SPI9_CS2: TP17.1 U8.148(PH[4]) ; port SPI9.CS2
SPI9_CS4: TP16.1 U8.150(PH[9]) ; port SPI9.CS4
SPI9_CS5: TP15.1 U8.151(PH[8]) ; port SPI9.CS5
SPI9_MISO: D20.C R120.2 TP13.1 ; port SPI9.MISO
SPI9_MOSI: R119.2 TP12.1 ; port SPI9.MOSI
SPI9_SCK: R121.2 TP14.1 ; port SPI9.SCK
STDBY_NOT_A: R204.2 ; port STDBY_NOT_A
STDBY_NOT_B: R205.2 ; port STDBY_NOT_B
TEST0_LED: R142.1 TP41.1 U8.7(PC[5])
UART_RX: R196.1 TP2.1 U8.23(PI[9])
UART_TX: R195.1 TP1.1 U8.22(PI[8])
VCC_EXT_MON: R146.2 U8.49(PG[7])
VCCA_MON: R147.2 U8.39(PI[2])
VCCB_MON: R148.2 U8.56(PG[10])
WDI: U8.4(PC[8]) ; port WDI
WK_LPM: U8.5(PC[7]) ; port WAKE_LPM
NetC60_1: C60.1 U8.103(XTAL) X1.1
NetC61_1: C61.1 U8.102(EXTAL) X1.3
NetD12_A: D12.A R122.2 R123.2
NetD13_A: D13.A R128.2 R130.2
NetJP6_1: JP6.1 R169.1 R179.1
NetLED1_A: LED1.A R138.2
NetLED2_A: LED2.A R142.2
NetLED8_A: LED8.A R195.2
NetLED9_A: LED9.A R196.2
NetLED10_C: LED10.C R202.2
NetR119_1: R119.1 U8.149(PH[10])
NetR120_1: R120.1 U8.145(PE[10])
NetR121_1: R121.1 U8.144(PH[2])
NetR123_1: R123.1 U8.133(PA[2])
NetR124_1: R124.1 U8.132(PE[9])
NetR125_1: R125.1 U8.130(PD[5])
NetR126_1: R126.1 U8.129(PD[4])
NetR129_1: R129.1 U8.121(PORST)
NetR130_1: R130.1 U8.120(PA[4])
NetR131_2: R131.2 U8.16(PE[2])
NetR132_2: R132.2 U8.17(PD[12])
NetR133_2: R133.2 U8.18(PD[13])
NetR135_1: R135.1 U8.98(PF[12])
NetR136_1: R136.1 U8.96(PF[10])
NetR137_1: R137.1 U8.95(PF[9])
NetR139_1: R139.1 U8.71(PI[12])
NetR140_1: R140.1 U8.73(PI[10])
NetR141_1: R141.1 U8.75(PF[0])
NetR143_1: R143.1 R146.1 R149.1
NetR144_1: R144.1 R147.1 R150.1
NetR145_1: R145.1 R148.1 R151.1
NetR169_2: R169.2 U8.44(PG[6])
NetR204_1: R204.1 U8.140(PH[0])
NetR205_1: R205.1 U8.105(PI[14])

Not connected (* = marked no-connect by the designer): J1 7(EVTI)* 8(nc)* 13(RDY)*; U8 10(PL[8])* 28(PG[1])* 29(PG[2])* 30(PG[3])* 36(PB[5])* 37(PI[0])* 38(PI[1])* 40(PI[3])* 41(PI[4])* 42(PI[5])* 43(PG[5])* 45(PB[7]) 46(PB[6])* 47(PI[6])* 48(PI[7])* 50(PG[8])* 55(PG[9])* 57(PG[11])* 58(PG[12])* 59(PE[15])* 65(PB[2])* 66(PB[1])* 67(PB[0])* 122(ESR0)*

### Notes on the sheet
- @{"Id":"JCBNWSNT\QPDSOGVQ","ObjectType":2} is 40Mhz crystal in 3.2x2.5mm SMD package
  @{"Id":"JCBNWSNT\LBNJKZAU","ObjectType":2} and @{"Id":"JCBNWSNT\IEZMZNIT","ObjectType":2} to sized according to selected crystal
- (near TP3) 3V3 supply pin for UART communication

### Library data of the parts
C60 C61 = 10pF/50V_10%_0603: 10pF Ceramic capacitor; Tolerance: 10%; T.Min: -55C; T.Max: 125C; Type: C0G/NP0
D12 D13 D20-D24 = BAT54-Y: Automotive small signal Schottky diodes; pin to pad: A>1 C>3; Forward Drop: 0,5V; T.Min: -40C; T.Max: 150C; Value: 40V; Current: 0.3A
LED1 = LED/RED_00603: Forward Drop: 2V; Current: 30mA
LED2 LED8-LED10 = LED/ORANGE_0603: Forward Drop: 2,1V; Current: 30mA
R119-R121 R124-R126 R131-R133 R135-R137 R139-R141 = 47R/0.1W_5%_0603: Resistor SMD; Tolerance: 5%; Power: 0.1W
R122 R128 R179 = 47k/0.1W_5%_0603: Resistor SMD; Tolerance: 5%; Power: 0.1W
R123 R129 R130 R146-R151 R169 = 15k/0.1W_5%_0603: Resistor SMD; Tolerance: 5%; Power: 0.1W
R127 = 4k7/0.1W_5%_0603: Resistor SMD; Tolerance: 5%; Power: 0.1W
R134 = 10k/0.1W_5%_0603: SMD Resistor Automotive; 2B Part Number: 2BRESCHIPSF00800; Manufacturer: PANASONIC; Manufacturer P/N: ERJP03F1002V; Tolerance: 1%; Power: 0.1W
R138 R142 R202 = 1k5/0.1W_5%_0603: Resistor SMD; Tolerance: 5%; Power: 0.1W
R143-R145 = 100k/0.1W_5%_0603: SMD Resistor; 2B Part Number: 2BRESCHIPSF00800; Manufacturer: PANASONIC; Manufacturer P/N: ERJP03F1002V; Tolerance: 1%; Power: 0.1W
R195 R196 = 2k7/0.1W_5%_0603: Resistor SMD; Tolerance: 5%; Power: 0.1W
R204 R205 = 47R/0.1W_5%_0603: Resistor SMD 0603; Tolerance: 5%; Power: 0.1W
TP1-TP4 TP9 TP12-TP21 TP24-TP49 TP51-TP53 = Test Point_1: PCB ring test point - black (drill 1.32mm); 2B Part Number: 2BCONTESTPF00021; Manuf Code: 262-2214; Manufacturer: RS PRO
U8 = SPC58NG84E7: Chorus 6M, 3 cores, 6MB flash, LQFP176 package
X1 = CX3225CA40000D0HSSZ1: CRYSTAL 40.000MHZ 8PF SMD Automotive -40/+125

## Sheet PMIC.SchDoc: ST PDU - PMIC
size A3; Author: EMEA - ADG - M&A; Organization: STMicroelectronics; Address1: Pobrezni 3; Address2: 186 00  Prague 8; Address3: Czech Republic; Revision: 2.3; SheetNumber: 12; SheetTotal: 14
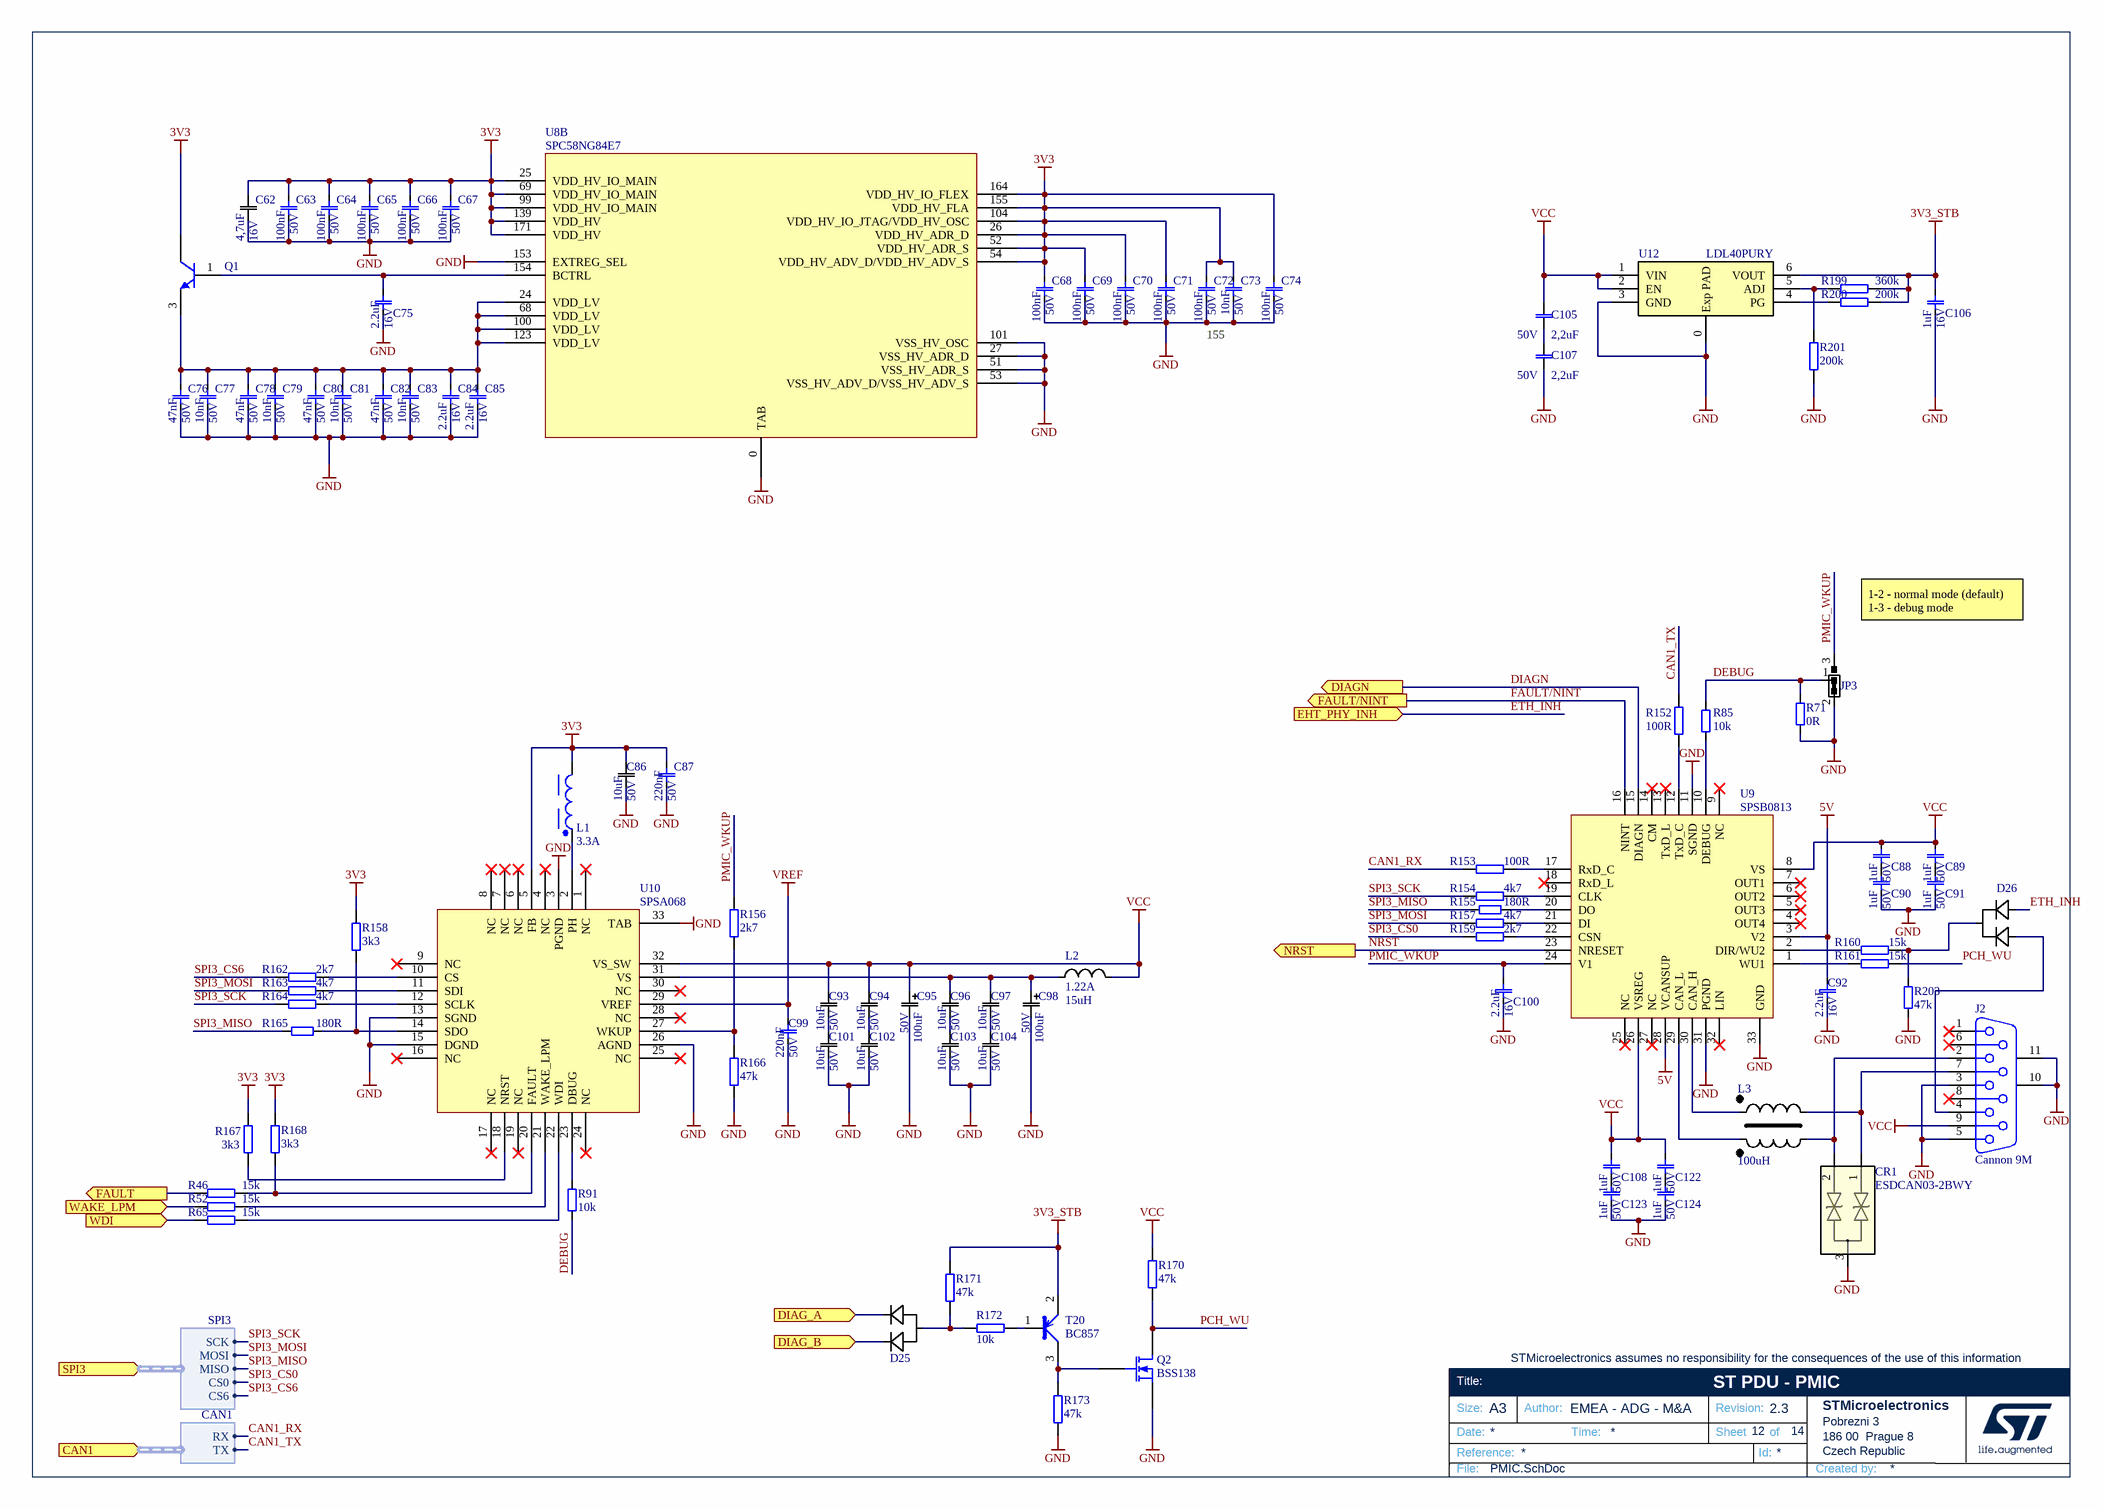
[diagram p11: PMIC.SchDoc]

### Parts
C62  Voltage: 16V  [R0805_ROUND]  (hidden comment: 4,7uF)
C63  Voltage: 50V  [C0603_ROUND]  (hidden comment: 100nF)
C64  Voltage: 50V  [C0603_ROUND]  (hidden comment: 100nF)
C65  Voltage: 50V  [C0603_ROUND]  (hidden comment: 100nF)
C66  Voltage: 50V  [C0603_ROUND]  (hidden comment: 100nF)
C67  Voltage: 50V  [C0603_ROUND]  (hidden comment: 100nF)
C68  Voltage: 50V  [C0603_ROUND]  (hidden comment: 100nF)
C69  Voltage: 50V  [C0603_ROUND]  (hidden comment: 100nF)
C70  Voltage: 50V  [C0603_ROUND]  (hidden comment: 100nF)
C71  Voltage: 50V  [C0603_ROUND]  (hidden comment: 100nF)
C72  Voltage: 50V  [C0603_ROUND]  (hidden comment: 100nF)
C73  Voltage: 50V  [C0603_ROUND]  (hidden comment: 10nF)
C74  Voltage: 50V  [C0603_ROUND]  (hidden comment: 100nF)
C75  Voltage: 16V  [C0603_ROUND]  (hidden comment: 2.2uF)
C76  Voltage: 50V  [C0603_ROUND]  (hidden comment: 47nF)
C77  Voltage: 50V  [C0603_ROUND]  (hidden comment: 10nF)
C78  Voltage: 50V  [C0603_ROUND]  (hidden comment: 47nF)
C79  Voltage: 50V  [C0603_ROUND]  (hidden comment: 10nF)
C80  Voltage: 50V  [C0603_ROUND]  (hidden comment: 47nF)
C81  Voltage: 50V  [C0603_ROUND]  (hidden comment: 10nF)
C82  Voltage: 50V  [C0603_ROUND]  (hidden comment: 47nF)
C83  Voltage: 50V  [C0603_ROUND]  (hidden comment: 10nF)
C84  Voltage: 16V  [C0603_ROUND]  (hidden comment: 2.2uF)
C85  Voltage: 16V  [C0603_ROUND]  (hidden comment: 2.2uF)
C86  Voltage: 50V  [C1206_ROUND]  (hidden comment: 10uF)
C87  Voltage: 50V  [C0603_ROUND]  (hidden comment: 220nF)
C88  Voltage: 50V  [C0603_ROUND]  (hidden comment: 1uF)
C89  Voltage: 50V  [C0603_ROUND]  (hidden comment: 1uF)
C90  Voltage: 50V  [C0603_ROUND]  (hidden comment: 1uF)
C91  Voltage: 50V  [C0603_ROUND]  (hidden comment: 1uF)
C92  Voltage: 16V  [C0603_ROUND]  (hidden comment: 2.2uF)
C93  Voltage: 50V  [C1206_ROUND]  (hidden comment: 10uF)
C94  Voltage: 50V  [C1206_ROUND]  (hidden comment: 10uF)
C95  Voltage: 50V  [C_EL 10x10.5mm VP]  (hidden comment: 100uF)
C96  Voltage: 50V  [C1206_ROUND]  (hidden comment: 10uF)
C97  Voltage: 50V  [C1206_ROUND]  (hidden comment: 10uF)
C98  Voltage: 50V  [C_EL 10x10.5mm VP]  (hidden comment: 100uF)
C99  Voltage: 50V  [C0603_ROUND]  (hidden comment: 220nF)
C100  Voltage: 16V  [C0603_ROUND]  (hidden comment: 2.2uF)
C101  Voltage: 50V  [C1206_ROUND]  (hidden comment: 10uF)
C102  Voltage: 50V  [C1206_ROUND]  (hidden comment: 10uF)
C103  Voltage: 50V  [C1206_ROUND]  (hidden comment: 10uF)
C104  Voltage: 50V  [C1206_ROUND]  (hidden comment: 10uF)
C105  Voltage: 50V  [C0805_ROUND]  (hidden comment: 2,2uF)
C106  Voltage: 16V  [C0603_ROUND]  (hidden comment: 1uF)
C107  Voltage: 50V  [C0805_ROUND]  (hidden comment: 2,2uF)
C108  Voltage: 50V  [C0603_ROUND]  (hidden comment: 1uF)
C122  Voltage: 50V  [C0603_ROUND]  (hidden comment: 1uF)
C123  Voltage: 50V  [C0603_ROUND]  (hidden comment: 1uF)
C124  Voltage: 50V  [C0603_ROUND]  (hidden comment: 1uF)
CR1  ESDCAN03-2BWY  [SOT323-3L_STM]
D25  BAT54A  [SOT323-3L_STM]  (value not drawn)
D26  BAT54-Y  [SOT323-3L_STM]  (value not drawn)
J2  Cannon 9M  [DSUB_9M]
JP3  JUMP_3_PIN  [JUMP_3]  (value not drawn)
L1  Rated Current: 3.3A  [WE-MAPI_5030]  (hidden comment: 10uH, 3.3A)
L2  Rated Current: 1.22A  [IND_LPS6235_COC]  (hidden comment: 15uH)
L3  value 100uH  [CAN_CMC]  (hidden comment: B82789C0104N001)
Q1  BC68PA  [DFN2020-3]  (value not drawn)
Q2  BSS138  [SOT323-3L_STM]
R46  15k  [R0603_round]
R52  15k  [R0603_round]
R65  15k  [R0603_round]
R71  0R  [R0603_round]
R85  10k  [R0603_round]
R91  10k  [R0603_round]
R152  100R  [R0603_round]
R153  100R  [R0603_round]
R154  4k7  [R0603_round]
R155  180R  [R0603_round]
R156  2k7  [R0603_round]
R157  4k7  [R0603_round]
R158  3k3  [R0603_round]
R159  2k7  [R0603_round]
R160  15k  [R0603_round]
R161  15k  [R0603_round]
R162  2k7  [R0603_round]
R163  4k7  [R0603_round]
R164  4k7  [R0603_round]
R165  180R  [R0603_round]
R166  47k  [R0603_round]
R167  3k3  [R0603_round]
R168  3k3  [R0603_round]
R170  47k  [R0603_round]
R171  47k  [R0603_round]
R172  10k  [R0603_round]
R173  47k  [R0603_round]
R199  360k  [R0603_round]
R200  200k  [R0603_round]
R201  200k  [R0603_round]
R203  47k  [R0603_round]
T20  BC857  [SOT323-3L_STM]
U8  SPC58NG84E7  [eLQFP176 (LQFP176L2600X2600-176)]  (part B of 2)
U9  SPSB0813  [QFN32L_5x5_STM-M]
U10  SPSA068  [QFN32_5X5MM_STM]
U12  LDL40PURY  [DFN6_2X2_STM]

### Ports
CAN1 (in, harness CAN1, see TOP_level[3C], MCU[2A]), DIAG_A (in, see TOP_level[3D], GroupA[4D], MCU[1B]), DIAG_B (in, see TOP_level[3D], GroupB[4D], MCU[8B]), DIAGN (out, see TOP_level[3C], MCU[2A]), EHT_PHY_INH (in, see TOP_level[3D]), FAULT (out, see TOP_level[3C], MCU[2A]), FAULT/NINT (out, see TOP_level[3C], MCU[2A]), NRST (out, see TOP_level[3C], MCU[2A]), SPI3 (in, harness SPI3, see TOP_level[3C], MCU[2A]), WAKE_LPM (in, see TOP_level[3C], MCU[2A]), WDI (in, see TOP_level[3C], MCU[2A])

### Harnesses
SPI3: SCK, MOSI, MISO, CS0, CS6
CAN1: RX, TX

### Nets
3V3: C62.2 C63.2 C64.2 C65.2 C66.2 C67.2 C68.2 C69.2 C70.2 C71.2 C72.2 C73.2 C74.2 C86.2 C87.2 L1.2 Q1.2(C) R158.1 R167.1 R168.1 U8.25(VDD_HV_IO_MAIN) U8.26(VDD_HV_ADR_D) U8.52(VDD_HV_ADR_S) U8.54(VDD_HV_ADV_D/VDD_HV_ADV_S) U8.69(VDD_HV_IO_MAIN) U8.99(VDD_HV_IO_MAIN) U8.104(VDD_HV_IO_JTAG/VDD_HV_OSC) U8.139(VDD_HV) U8.155(VDD_HV_FLA) U8.164(VDD_HV_IO_FLEX) U8.171(VDD_HV) U10.5(FB)
3V3_STB: C106.2 R171.1 R199.1 R200.2 T20.2(E) U12.6(VOUT)
5V: C92.2 U9.3(V2) U9.28(VCANSUP)
GND: C62.1 C63.1 C64.1 C65.1 C66.1 C67.1 C68.1 C69.1 C70.1 C71.1 C72.1 C73.1 C74.1 C75.1 C76.1 C77.1 C78.1 C79.1 C80.1 C81.1 C82.1 C83.1 C84.1 C85.1 C86.1 C87.1 C90.1 C91.1 C92.1 C95.2 C98.2 C99.1 C100.1 C101.1 C102.1 C103.1 C104.1 C106.1 C107.1 C123.1 C124.1 CR1.3 J2.3 J2.5 J2.10(MH1) J2.11(MH2) JP3.2 Q2.2(S) R71.1 R166.2 R173.2 R201.1 R203.1 U8.0(TAB) U8.27(VSS_HV_ADR_D) U8.51(VSS_HV_ADR_S) U8.53(VSS_HV_ADV_D/VSS_HV_ADV_S) U8.101(VSS_HV_OSC) U8.153(EXTREG_SEL) U9.11(SGND) U9.31(PGND) U9.33(GND) U10.3(PGND) U10.13(SGND) U10.15(DGND) U10.26(AGND) U10.33(TAB) U12.0(Exp_PAD) U12.3(GND)
VCC: C88.2 C89.2 C93.2 C94.2 C95.1 C105.2 C108.2 C122.2 J2.9 L2.2 R170.1 U9.8(VS) U9.26(VSREG) U10.32(VS_SW) U12.1(VIN) U12.2(EN)
VREF: C99.2 U10.29(VREF)
CAN1_RX: R153.1 ; port CAN1.RX
CAN1_TX: R152.2 ; port CAN1.TX
DEBUG: JP3.1 R71.2 R85.2 R91.1
DIAG_A: D25.1 ; port DIAG_A
DIAG_B: D25.2 ; port DIAG_B
DIAGN: U9.15(DIAGN) ; port DIAGN
ETH_INH: D26.2 ; port EHT_PHY_INH
FAULT: R46.2 ; port FAULT
FAULT/NINT: U9.16(NINT) ; port FAULT/NINT
NRST: U9.23(NRESET) ; port NRST
PCH_WU: Q2.3(D) R161.2 R170.2
PMIC_WKUP: C100.2 JP3.3 R156.1 U9.24(V1)
SPI3_CS0: R159.2 ; port SPI3.CS0
SPI3_CS6: R162.2 ; port SPI3.CS6
SPI3_MISO: R155.2 R165.2 ; port SPI3.MISO
SPI3_MOSI: R157.1 R163.1 ; port SPI3.MOSI
SPI3_SCK: R154.1 R164.1 ; port SPI3.SCK
WDI: R65.2 ; port WDI
WK_LPM: R52.2 ; port WAKE_LPM
NetC75_2: C75.2 Q1.1(B) U8.154(BCTRL)
NetC76_2: C76.2 C77.2 C78.2 C79.2 C80.2 C81.2 C82.2 C83.2 C84.2 C85.2 Q1.3(E) U8.24(VDD_LV) U8.68(VDD_LV) U8.100(VDD_LV) U8.123(VDD_LV)
NetC88_1: C88.1 C90.2
NetC89_1: C89.1 C91.2
NetC93_1: C93.1 C101.2
NetC94_1: C94.1 C102.2
NetC96_1: C96.1 C103.2
NetC96_2: C96.2 C97.2 C98.1 L2.1 U10.31(VS)
NetC97_1: C97.1 C104.2
NetC105_1: C105.1 C107.2
NetC108_1: C108.1 C123.2
NetC122_1: C122.1 C124.2
NetCR1_1: CR1.1 J2.7 L3.4
NetCR1_2: CR1.2 J2.2 L3.1
NetD25_3: D25.3 R171.2 R172.2
NetD26_1: D26.1 J2.4
NetD26_3: D26.3 R160.2 R203.2
NetL1_1: L1.1 U10.2(PH)
NetL3_2: L3.2 U9.29(CAN_L)
NetL3_3: L3.3 U9.30(CAN_H)
NetQ2_1: Q2.1(G) R173.1 T20.3(C)
NetR46_1: R46.1 R168.2 U10.20(FAULT)
NetR52_1: R52.1 U10.21(WAKE_LPM)
NetR65_1: R65.1 U10.22(WDI)
NetR85_1: R85.1 U9.10(DEBUG)
NetR91_2: R91.2 U10.23(DBUG)
NetR152_1: R152.1 U9.12(TxD_C)
NetR153_2: R153.2 U9.17(RxD_C)
NetR154_2: R154.2 U9.19(CLK)
NetR155_1: R155.1 U9.20(DO)
NetR156_2: R156.2 R166.1 U10.27(WKUP)
NetR157_2: R157.2 U9.21(DI)
NetR158_2: R158.2 R165.1 U10.14(SDO)
NetR159_1: R159.1 U9.22(CSN)
NetR160_1: R160.1 U9.2(DIR/WU2)
NetR161_1: R161.1 U9.1(WU1)
NetR162_1: R162.1 U10.10(CS)
NetR163_2: R163.2 U10.11(SDI)
NetR164_2: R164.2 U10.12(SCLK)
NetR167_2: R167.2 U10.18(NRST)
NetR172_1: R172.1 T20.1(B)
NetR199_2: R199.2 R201.2 U12.5(ADJ)
NetR200_1: R200.1 U12.4(PG)

Not connected (* = marked no-connect by the designer): J2 1* 6* 8*; U9 4(OUT4)* 5(OUT3)* 6(OUT2)* 7(OUT1)* 9(NC)* 13(TxD_L)* 14(CM)* 18(RxD_L)* 25(NC)* 27(NC)* 32(LIN)*; U10 1(NC)* 4(NC)* 6(NC)* 7(NC)* 8(NC)* 9(NC)* 16(NC)* 17(NC)* 19(NC)* 24(NC)* 25(NC)* 28(NC)* 30(NC)*

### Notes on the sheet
- 155
- 1-2 - normal mode (default)
  1-3 - debug mode

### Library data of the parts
C62 = 4,7uF/16V_10%_0805: 4,7uF Ceramic capacitor; Tolerance: 10%; T.Min: -55C; T.Max: 125C; Type: X7R; Model: EMK212B7475KG-T
C63-C72 C74 = 100nF/50V_10%_0603: as C8 on sheet VNF9D5SF
C73 C77 C79 C81 C83 = 10nF/50V_10%_0603: as C13 on sheet VNF9D5SF
C75 C84 C85 C92 C100 = 2.2uF/16V_10%_0603: as C12 on sheet VNF9D5SF
C76 C78 C80 C82 = 47nF/50V_10%_0603: 47nF Ceramic capacitor; Tolerance: 10%; T.Min: -55C; T.Max: 125C; Type: X7R
C86 C93 C94 C96 C97 C101-C104 = 10uF/50V_10%_1206: 10uF Ceramic capacitor; Tolerance: 10%; T.Min: -55C; T.Max: 125C; Type: X7R
C87 C99 = 220nF/50V_10%_0603: as C10 on sheet VNF9D5SF
C88-C91 C108 C122-C124 = 1uF/50V_10%_0603: 1uF Ceramic capacitor; Tolerance: 10%; T.Min: -55C; T.Max: 125C; Type: X7R
C95 C98 = 100uF/50V_20%_CES_D_10: 100uF Electrolytic capacitor (EEHZC1H101V); Tolerance: 20%; T.Min: -55C; T.Max: 125C; Type: Conductive Polymer Hybrid Aluminum Electrolytic Capacitor
C105 C107 = 2,2uF/50V_10%_0805: 2,2uF Ceramic capacitor; Tolerance: 10%; T.Min: -55C; T.Max: 125C; Type: X7R
C106 = 1uF/16V_10%_0603: 1uF Ceramic capacitor; Tolerance: 10%; T.Min: -55C; T.Max: 125C; Type: X7R
CR1 = ESDCAN03-2BWY: No Description Available; Mfr_Name: STMicroelectronics; Type: DEV
D25 = BAT54A: as D3 on sheet VNF9D5SF
D26 = BAT54C: as D16 on sheet GroupB
J2 = Cannon 9M: Header, 9-Pin, Right Angle
L1 = 74438367100: WE-MAPI, size 5030, 10uH, 3.3A, 70.2mOhm; Manufacturer: Wurth Elektronik; DC Resistance: 61mOhm; Saturation Current: 4.8A; Case/Size Code: 5030; Self Resonant Frequency: 13MHz
L2 = LPS6235-153: SMD Inductor; 15uH/20%/2,0A sat.; 6x6x3,5mm; Tolerance: 20%; DC resistance: 0,125 Ohm; T.Min: -40C; T.Max: 165C; Type: Composite Core, Shielded; Saturation Current: 2,0A
L3 = 100uH/0,15A_+50%/-30%_1812: Common Mode Choke for CAN; Tolerance: +50/-30; DC resistance: 1,5 Ohm; T.Min: -55C; T.Max: 125C; Type: Ferrite Core, Shielded; Rated Current: 0,15A
Q1 = BC68PA: NPN Medium Power Transistor
Q2 = BSS138: N-Channel Enhancement Mode Vertical DMOS FET
R46 R52 R65 R160 R161 = 15k/0.1W_5%_0603: Resistor SMD; Tolerance: 5%; Power: 0.1W
R71 = 0R/0.1W_5%_0603: Resistor SMD 0805; Tolerance: 5%; Power: 0.1W
R85 R91 = 10k/0.1W_5%_0603: Resistor SMD 0603; 2B Part Number: 2BRESCHIPSF00800; Manufacturer: PANASONIC; Manufacturer P/N: ERJP03F1002V; Tolerance: 1%; Power: 0.1W
R152 R153 = 100R/0.1W_5%_0603: Resistor SMD; Tolerance: 5%; Power: 0.1W
R154 R157 R163 R164 = 4k7/0.1W_5%_0603: Resistor SMD; Tolerance: 5%; Power: 0.1W
R155 R165 = 180R/0.1W_5%_0603: as R27 on sheet VNF9D5SF
R156 R159 R162 = 2k7/0.1W_5%_0603: Resistor SMD; Tolerance: 5%; Power: 0.1W
R158 R167 R168 = 3k3/0.1W_5%_0603: Resistor SMD; Tolerance: 5%; Power: 0.1W
R166 R170 R171 R173 = 47k/0.1W_5%_0603: Resistor SMD; Tolerance: 5%; Power: 0.1W
R172 = 10k/0.1W_5%_0603: as R134 on sheet MCU
R199 = 360k/0.1W_5%_0603: SMD Resistor; 2B Part Number: 2BRESCHIPSF00800; Manufacturer: PANASONIC; Manufacturer P/N: ERJP03F1002V; Tolerance: 1%; Power: 0.1W
R200 R201 = 200k/0.1W_5%_0603: SMD Resistor; 2B Part Number: 2BRESCHIPSF00800; Manufacturer: PANASONIC; Manufacturer P/N: ERJP03F1002V; Tolerance: 1%; Power: 0.1W
R203 = 47k/0.1W_5%_0603: Resistor SMD 0603; Tolerance: 5%; Power: 0.1W
T20 = BC857: PNP
U8 = SPC58NG84E7: as U8 on sheet MCU
U9 = SPSB081
U10 = SPSA068: SPSA068 PMIC with buck and precise voltage reference for MCU applications
U12 = LDL40PURY: Adjustable 200mA LDO

## Sheet Ethernet.SchDoc: ST PDU - Ethernet
size A4; Author: EMEA - ADG - M&A; Organization: STMicroelectronics; Address1: Pobrezni 3; Address2: 186 00  Prague 8; Address3: Czech Republic; Revision: 2.3; SheetNumber: 13; SheetTotal: 14
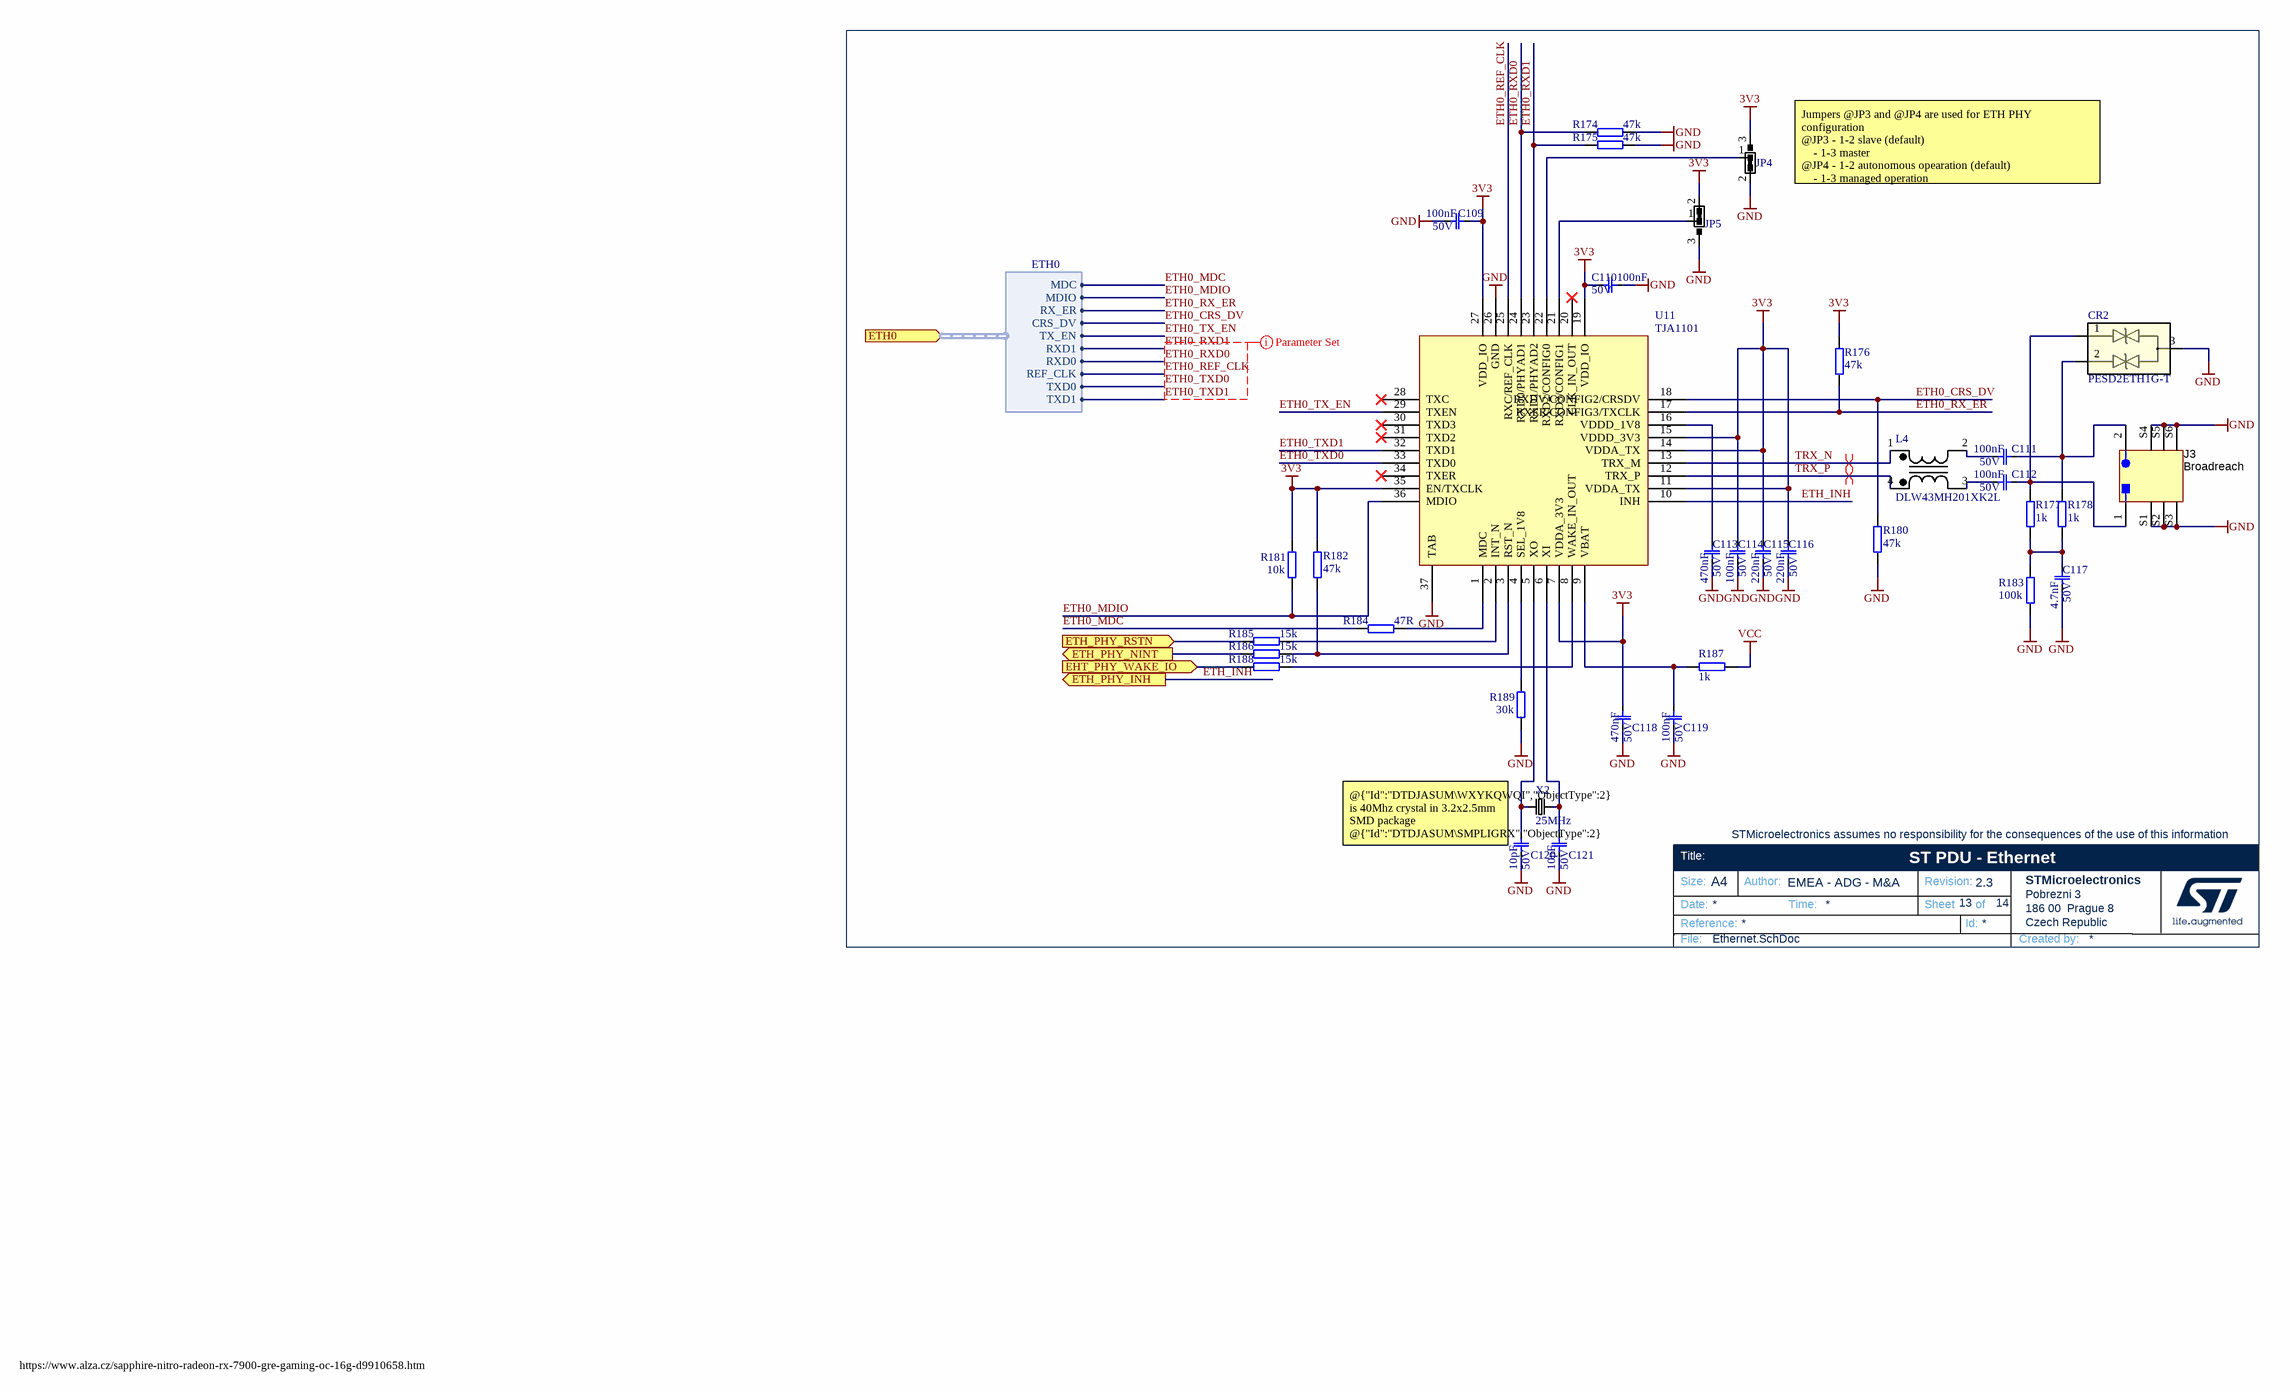
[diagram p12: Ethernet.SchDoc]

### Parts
C109  Voltage: 50V  [C0603_ROUND]  (hidden comment: 100nF)
C110  Voltage: 50V  [C0603_ROUND]  (hidden comment: 100nF)
C111  Voltage: 50V  [C0603_ROUND]  (hidden comment: 100nF)
C112  Voltage: 50V  [C0603_ROUND]  (hidden comment: 100nF)
C113  Voltage: 50V  [C0603_ROUND]  (hidden comment: 470nF)
C114  Voltage: 50V  [C0603_ROUND]  (hidden comment: 100nF)
C115  Voltage: 50V  [C0603_ROUND]  (hidden comment: 220nF)
C116  Voltage: 50V  [C0603_ROUND]  (hidden comment: 220nF)
C117  Voltage: 50V  [C0603_ROUND]  (hidden comment: 4.7nF)
C118  Voltage: 50V  [C0603_ROUND]  (hidden comment: 470nF)
C119  Voltage: 50V  [C0603_ROUND]  (hidden comment: 100nF)
C120  Voltage: 50V  [C0603_ROUND]  (hidden comment: 10pF)
C121  Voltage: 50V  [C0603_ROUND]  (hidden comment: 10pF)
CR2  PESD2ETH1G-T  [SOT23]
J3  Broadreach  [Broadreach connector - TE_2304372-2]
JP4  JUMP_3_PIN  [R0603_3JUMP]  (value not drawn)
JP5  JUMP_3_PIN  [R0603_3JUMP]  (value not drawn)
L4  DLW43MH201XK2L  [DLW43_MUR]
R174  47k  [R0603_round]
R175  47k  [R0603_round]
R176  47k  [R0603_round]
R177  1k  [R0603_round]
R178  1k  [R0603_round]
R180  47k  [R0603_round]
R181  10k  [R0603_round]
R182  47k  [R0603_round]
R183  100k  [R0603_round]
R184  47R  [R0603_round]
R185  15k  [R0603_round]
R186  15k  [R0603_round]
R187  1k  [R0603_round]
R188  15k  [R0603_round]
R189  30k  [R0603_round]
U11  TJA1101  [QFN 6x6]
X2  25MHz  [CRYSTAL_SMD_3.2x2.5mm]

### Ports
EHT_PHY_WAKE_IO (in, see TOP_level[3C], MCU[1C]), ETH0 (in, harness ETH0, see TOP_level[3C], MCU[1C]), ETH_PHY_INH (out, see TOP_level[3C]), ETH_PHY_NINT (out, see TOP_level[3C]), ETH_PHY_RSTN (in, see TOP_level[3C])

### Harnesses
ETH0: MDC, MDIO, RX_ER, RXD1, CRS_DV, RXD0, TX_EN, REF_CLK, TXD1, TXD0

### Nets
3V3: C109.2 C110.2 C114.2 C115.2 C116.2 C118.2 JP4.3 JP5.2 R176.1 R181.2 R182.1 U11.7(VDDA_3V3) U11.11(VDDA_TX) U11.14(VDDA_TX) U11.15(VDDD_3V3) U11.19(VDD_IO) U11.27(VDD_IO) U11.35(EN/TXCLK)
GND: C109.1 C110.1 C113.1 C114.1 C115.1 C116.1 C117.1 C118.1 C119.1 C120.1 C121.1 CR2.3 J3.S1(GND) J3.S2(GND) J3.S3(GND) J3.S4(GND) J3.S5(GND) J3.S6(GND) JP4.2 JP5.3 R174.1 R175.1 R180.1 R183.1 R189.1 U11.26(GND) U11.37(TAB)
VCC: R187.2
ETH0_CRS_DV: R180.2 U11.18(RXDV/CONFIG2/CRSDV) ; port ETH0.CRS_DV
ETH0_MDC: R184.1 ; port ETH0.MDC
ETH0_MDIO: R181.1 U11.36(MDIO) ; port ETH0.MDIO
ETH0_REF_CLK: U11.25(RXC/REF_CLK) ; port ETH0.REF_CLK
ETH0_RX_ER: R176.2 U11.17(RXER/CONFIG3/TXCLK) ; port ETH0.RX_ER
ETH0_RXD0: R174.2 U11.24(RXD0/PHYAD1) ; port ETH0.RXD0
ETH0_RXD1: R175.2 U11.23(RXD1/PHYAD2) ; port ETH0.RXD1
ETH0_TX_EN: U11.29(TXEN) ; port ETH0.TX_EN
ETH0_TXD0: U11.33(TXD0) ; port ETH0.TXD0
ETH0_TXD1: U11.32(TXD1) ; port ETH0.TXD1
ETH_INH: U11.10(INH) ; port ETH_PHY_INH
ETH_PHY_NINT: R186.1 ; port ETH_PHY_NINT
ETH_PHY_NRST: R185.1 ; port ETH_PHY_RSTN
ETH_PHY_WAKE_IO: R188.1 ; port EHT_PHY_WAKE_IO
TRX_N: L4.1 U11.13(TRX_M)
TRX_P: L4.4 U11.12(TRX_P)
NetC111_1: C111.1 L4.2
NetC111_2: C111.2 CR2.2 J3.2 R178.1
NetC112_1: C112.1 L4.3
NetC112_2: C112.2 CR2.1 J3.1 R177.1
NetC113_2: C113.2 U11.16(VDDD_1V8)
NetC117_2: C117.2 R177.2 R178.2 R183.2
NetC119_2: C119.2 R187.1 U11.9(VBAT)
NetC120_2: C120.2 U11.5(XO) X2.3
NetC121_2: C121.2 U11.6(XI) X2.1
NetJP4_1: JP4.1 U11.22(RXD2/CONFIG0)
NetJP5_1: JP5.1 U11.21(RXD3/CONFIG1)
NetR182_2: R182.2 R186.2 U11.3(RST_N)
NetR184_2: R184.2 U11.1(MDC)
NetR185_2: R185.2 U11.2(INT_N)
NetR188_2: R188.2 U11.8(WAKE_IN_OUT)
NetR189_2: R189.2 U11.4(SEL_1V8)

Not connected (* = marked no-connect by the designer): U11 20(CLK_IN_OUT)* 28(TXC)* 30(TXD3)* 31(TXD2)* 34(TXER)*

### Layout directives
differential pair: TRX_N, TRX_P
rule Matched Net Lengths [Tolerance = 3mm]; net class EHT__LENGTH_MATCH: ETH0_REF_CLK, ETH0_RXD0, ETH0_RXD1, ETH0_TXD0, ETH0_TXD1

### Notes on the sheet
- (near JP4) Jumpers @JP3 and @JP4 are used for ETH PHY configuration
  @JP3 - 1-2 slave (default)
  - 1-3 master
  @JP4 - 1-2 autonomous opearation (default)
  - 1-3 managed operation
- (near C120) @{"Id":"DTDJASUM\WXYKQWQI","ObjectType":2} is 40Mhz crystal in 3.2x2.5mm SMD package
  @{"Id":"DTDJASUM\SMPLIGRX","ObjectType":2} and @{"Id":"DTDJASUM\BLSLEWRE","ObjectType":2} to sized according to selected crystal
- https://www.alza.cz/sapphire-nitro-radeon-rx-7900-gre-gaming-oc-16g-d9910658.htm

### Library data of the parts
C109-C112 C114 C119 = 100nF/50V_10%_0603: as C8 on sheet VNF9D5SF
C113 C118 = 470nF/50V_10%_0603: 470nF Ceramic capacitor; Tolerance: 10%; T.Min: -55C; T.Max: 125C; Type: X7R
C115 C116 = 220nF/50V_10%_0603: as C10 on sheet VNF9D5SF
C117 = 4,7nF/50V_10%_0603: 4.7nF Ceramic capacitor; Tolerance: 10%; T.Min: -55C; T.Max: 125C; Type: X7R
C120 C121 = 10pF/50V_10%_0603: as C60 on sheet MCU
CR2 = PESD2ETH1G-T: ESD protection for automotive ethernet
J3 = CMP-0078655-1: Conn 1-Port 90° MATEnet Header, Code B; Manufacturer: TE Connectivity; 2B Part Number: 2BCONNECTPF00506; Manuf Code: 2304372-2
JP4 JP5 = JUMP_3_PIN: Value: 47k
L4 = DLW43MH201XK2L: Automotive ethernet CMMC; Mfr_Name: Murata; Type: Common Mode Chokes
R174-R176 R180 R182 = 47k/0.1W_5%_0603: Resistor SMD; Tolerance: 5%; Power: 0.1W
R177 R178 R187 = 1k/0.1W_5%_0603: Resistor SMD; Tolerance: 5%; Power: 0.1W
R181 = 10k/0.1W_5%_0603: as R134 on sheet MCU
R183 = 100k/0.1W_5%_0603: as R143 on sheet MCU
R184 = 47R/0.1W_5%_0603: Resistor SMD; Tolerance: 5%; Power: 0.1W
R185 R186 R188 = 15k/0.1W_5%_0603: Resistor SMD; Tolerance: 5%; Power: 0.1W
R189 = 30k/0.1W_5%_0603: Resistor SMD; Tolerance: 5%; Power: 0.1W
U11 = TJA1101: 100BASE-T1 PHY for Automotive Ethernet
X2 = CX3225CA25000D0HSSZ1: CRYSTAL 25.000MHZ 8PF SMD Automotive -40/+125

## Sheet Connectors.SchDoc: ST PDU - Power supply connection
size A4; Author: EMEA - ADG - M&A; Organization: STMicroelectronics; Address1: Pobrezni 3; Address2: 186 00  Prague 8; Address3: Czech Republic; Revision: 2.3; SheetNumber: 14; SheetTotal: 14
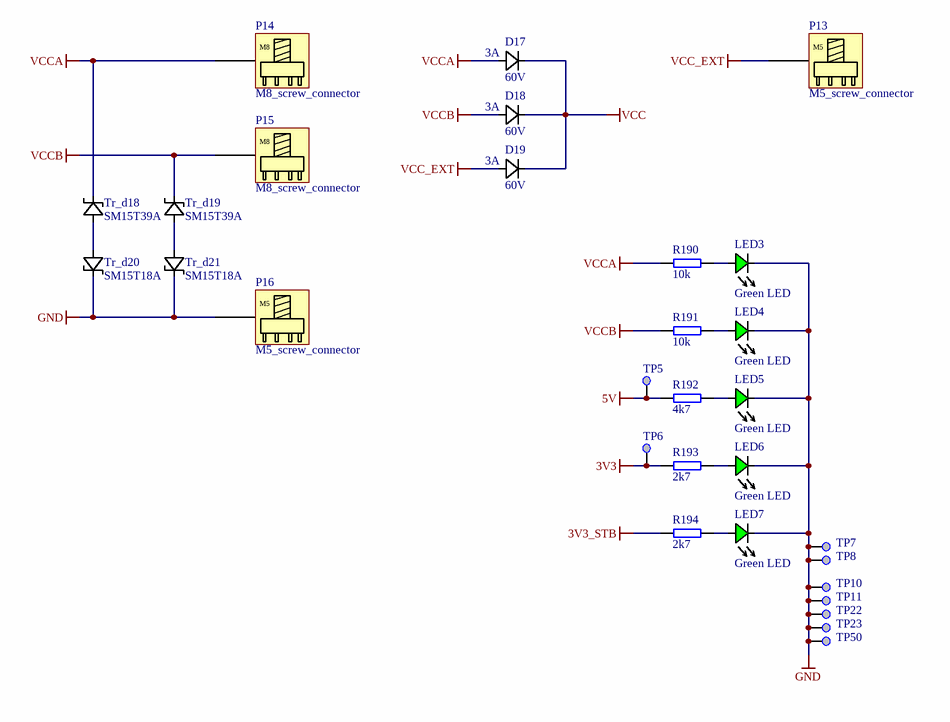
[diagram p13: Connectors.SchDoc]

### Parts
D17  value 60V  Current: 3A  [SOD128FLAT_STM]  (hidden comment: STPS360-Y)
D18  value 60V  Current: 3A  [SOD128FLAT_STM]  (hidden comment: STPS360-Y)
D19  value 60V  Current: 3A  [SOD128FLAT_STM]  (hidden comment: STPS360-Y)
LED3  Green LED  [D0603_ROUND]
LED4  Green LED  [D0603_ROUND]
LED5  Green LED  [D0603_ROUND]
LED6  Green LED  [D0603_ROUND]
LED7  Green LED  [D0603_ROUND]
P13  M5_screw_connector  [MTConn Power Tower M5]
P14  M8_screw_connector  [MTConn Power Tower M8]
P15  M8_screw_connector  [MTConn Power Tower M8]
P16  M5_screw_connector  [MTConn Power Tower M5]
R190  10k  [R0603_round]
R191  10k  [R0603_round]
R192  4k7  [R0603_round]
R193  2k7  [R0603_round]
R194  2k7  [R0603_round]
TP5  5V  [PIN]  (value not drawn)
TP6  3V3  [PIN]  (value not drawn)
TP7  GND  [PIN]  (value not drawn)
TP8  GND  [PIN]  (value not drawn)
TP10  GND  [PIN]  (value not drawn)
TP11  GND  [PIN]  (value not drawn)
TP22  GND  [PIN]  (value not drawn)
TP23  GND  [PIN]  (value not drawn)
TP50  GND  [PIN]  (value not drawn)
Tr_d18  SM15T39A  [SMC]
Tr_d19  SM15T39A  [SMC]
Tr_d20  SM15T18A  [SMC]
Tr_d21  SM15T18A  [SMC]

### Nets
3V3: R193.2 TP6.1
3V3_STB: R194.2
5V: R192.1 TP5.1
GND: LED3.C LED4.C LED5.C LED6.C LED7.C P16.1 TP7.1 TP8.1 TP10.1 TP11.1 TP22.1 TP23.1 TP50.1 Tr_d20.C Tr_d21.C
VCC: D17.C D18.C D19.C
VCC_EXT: D19.A P13.1
VCCA: D17.A P14.1 R190.2 Tr_d18.C
VCCB: D18.A P15.1 R191.2 Tr_d19.C
NetLED3_A: LED3.A R190.1
NetLED4_A: LED4.A R191.1
NetLED5_A: LED5.A R192.2
NetLED6_A: LED6.A R193.1
NetLED7_A: LED7.A R194.1
NetTr_d18_A: Tr_d18.A Tr_d20.A
NetTr_d19_A: Tr_d19.A Tr_d21.A

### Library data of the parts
D17-D19 = STPS360-Y: 60V/3A Automotive Schottky Diode STPS360-Y
LED3-LED7 = LED/GREEN_0603: Forward Drop: 2,1V; Current: 30mA
P13 P16 = M5_screw_connector: Pressfit M5 screw power connector (max 80A) with protector
P14 P15 = M8_screw_connector: as P7 on sheet GroupB
R190 R191 = 10k/0.1W_5%_0603: as R134 on sheet MCU
R192 = 4k7/0.1W_5%_0603: Resistor SMD; Tolerance: 5%; Power: 0.1W
R193 R194 = 2k7/0.1W_5%_0603: Resistor SMD; Tolerance: 5%; Power: 0.1W
TP5-TP8 TP10 TP11 TP22 TP23 TP50 = Test Point_1: as TP1 on sheet MCU
Tr_d18 Tr_d19 = SM15T39A: 39V 1500W unidirectional TVS in SMC; T.Min: -55C; T.Max: +150C
Tr_d20 Tr_d21 = SM15T18A: 18V 1500W unidirectional TVS in SMC; T.Min: -55C; T.Max: +150C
